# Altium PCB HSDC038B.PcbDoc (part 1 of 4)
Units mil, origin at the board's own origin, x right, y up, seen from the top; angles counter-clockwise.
Board outline 3620 x 4060 mil, 6 copper layers (Top Layer, Signal Layer 1, Signal Layer 2, Signal Layer 3, Signal Layer 4, Bottom Layer), stack 60.4 mil thick; 349 components, 209 nets, 1023 pads, 960 vias.
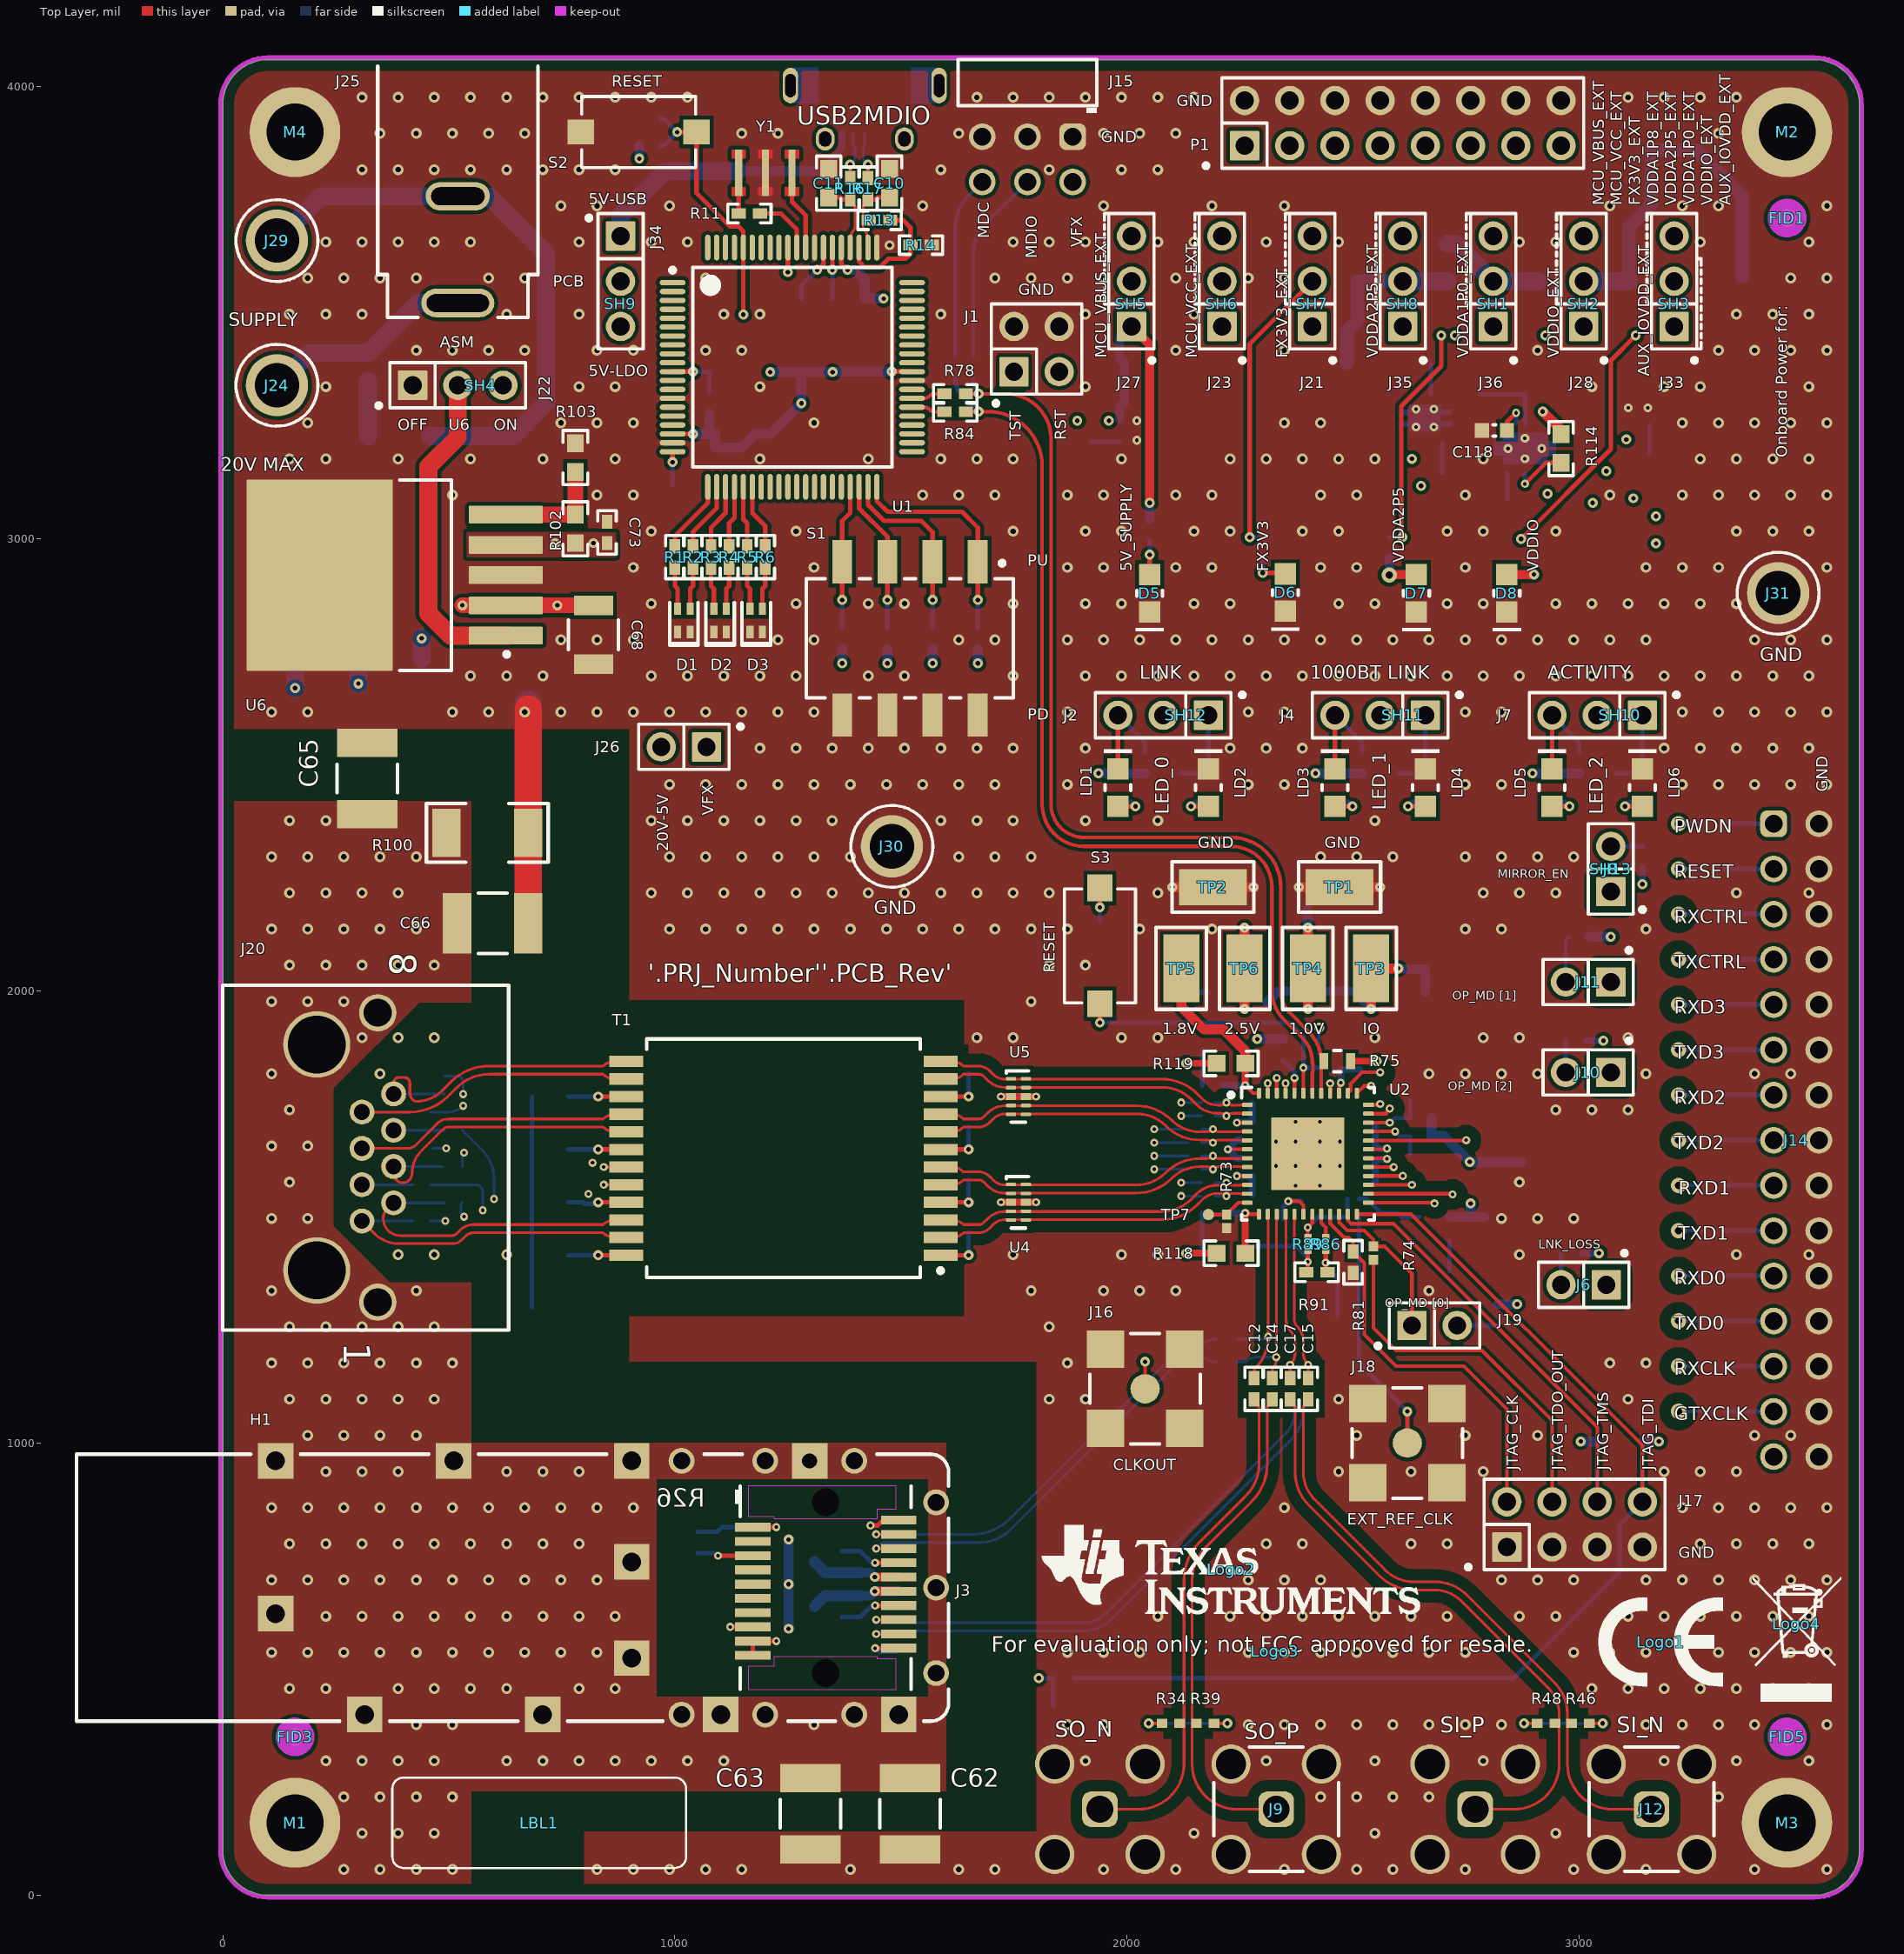
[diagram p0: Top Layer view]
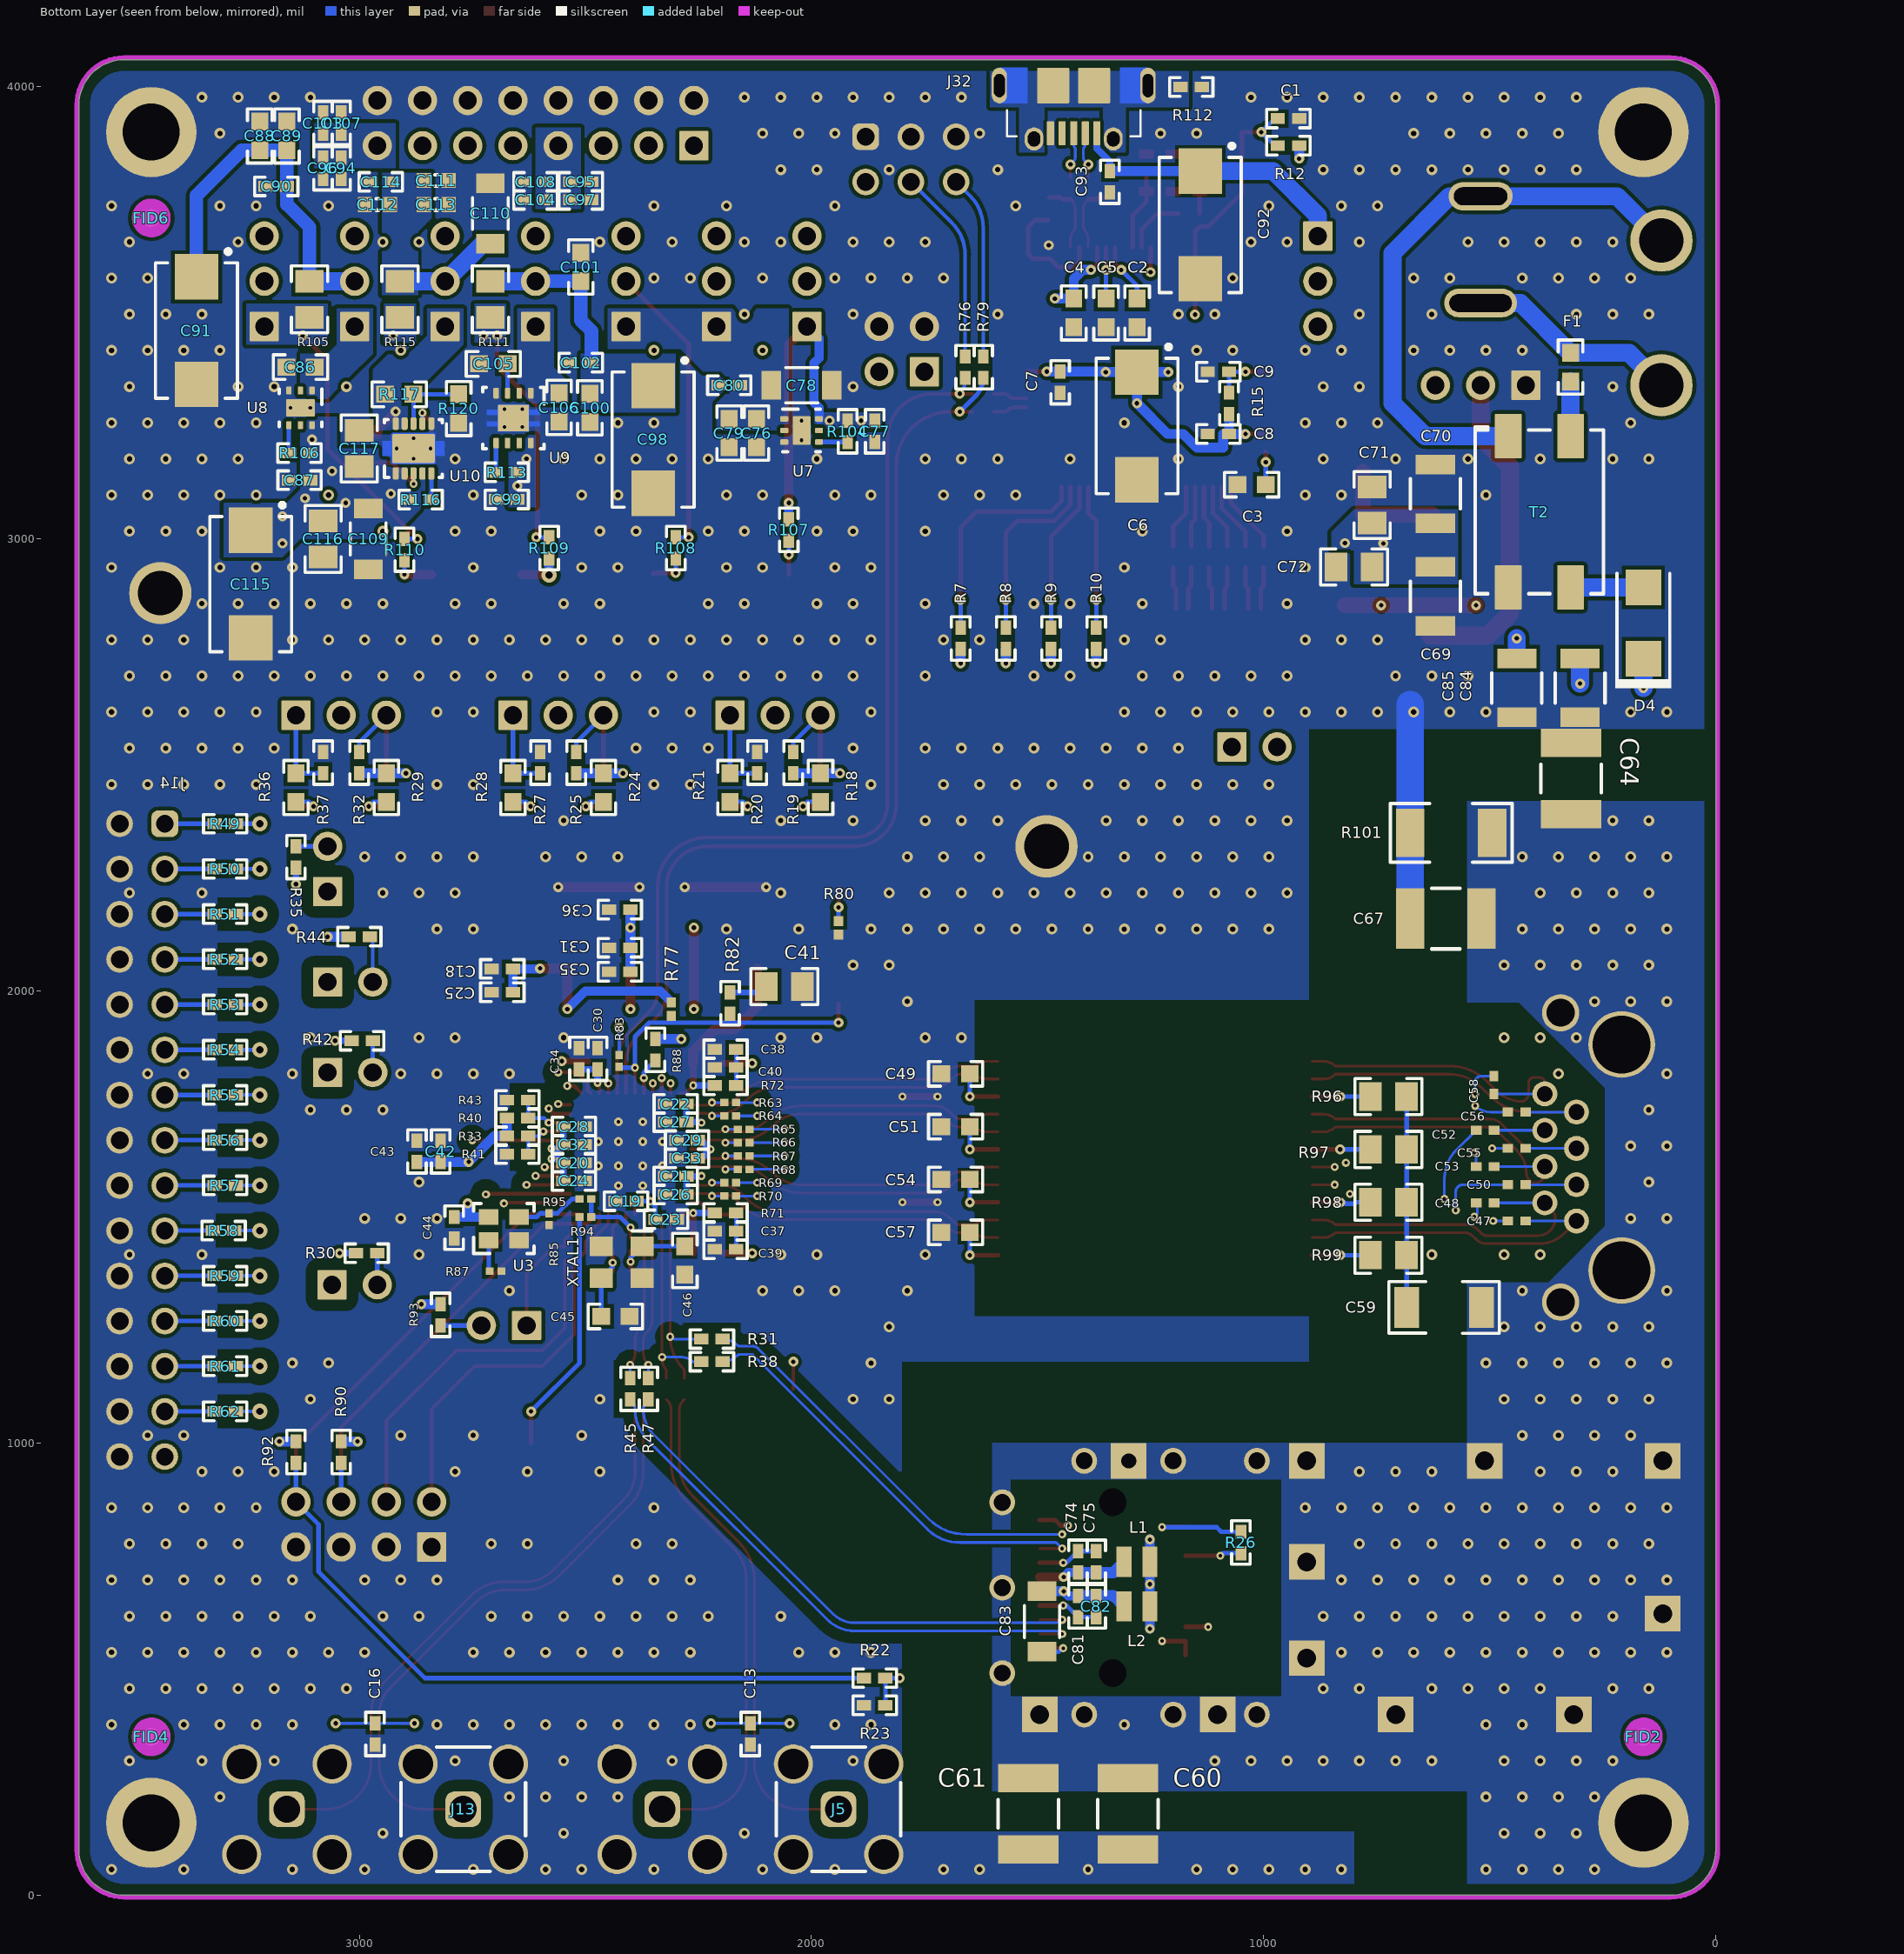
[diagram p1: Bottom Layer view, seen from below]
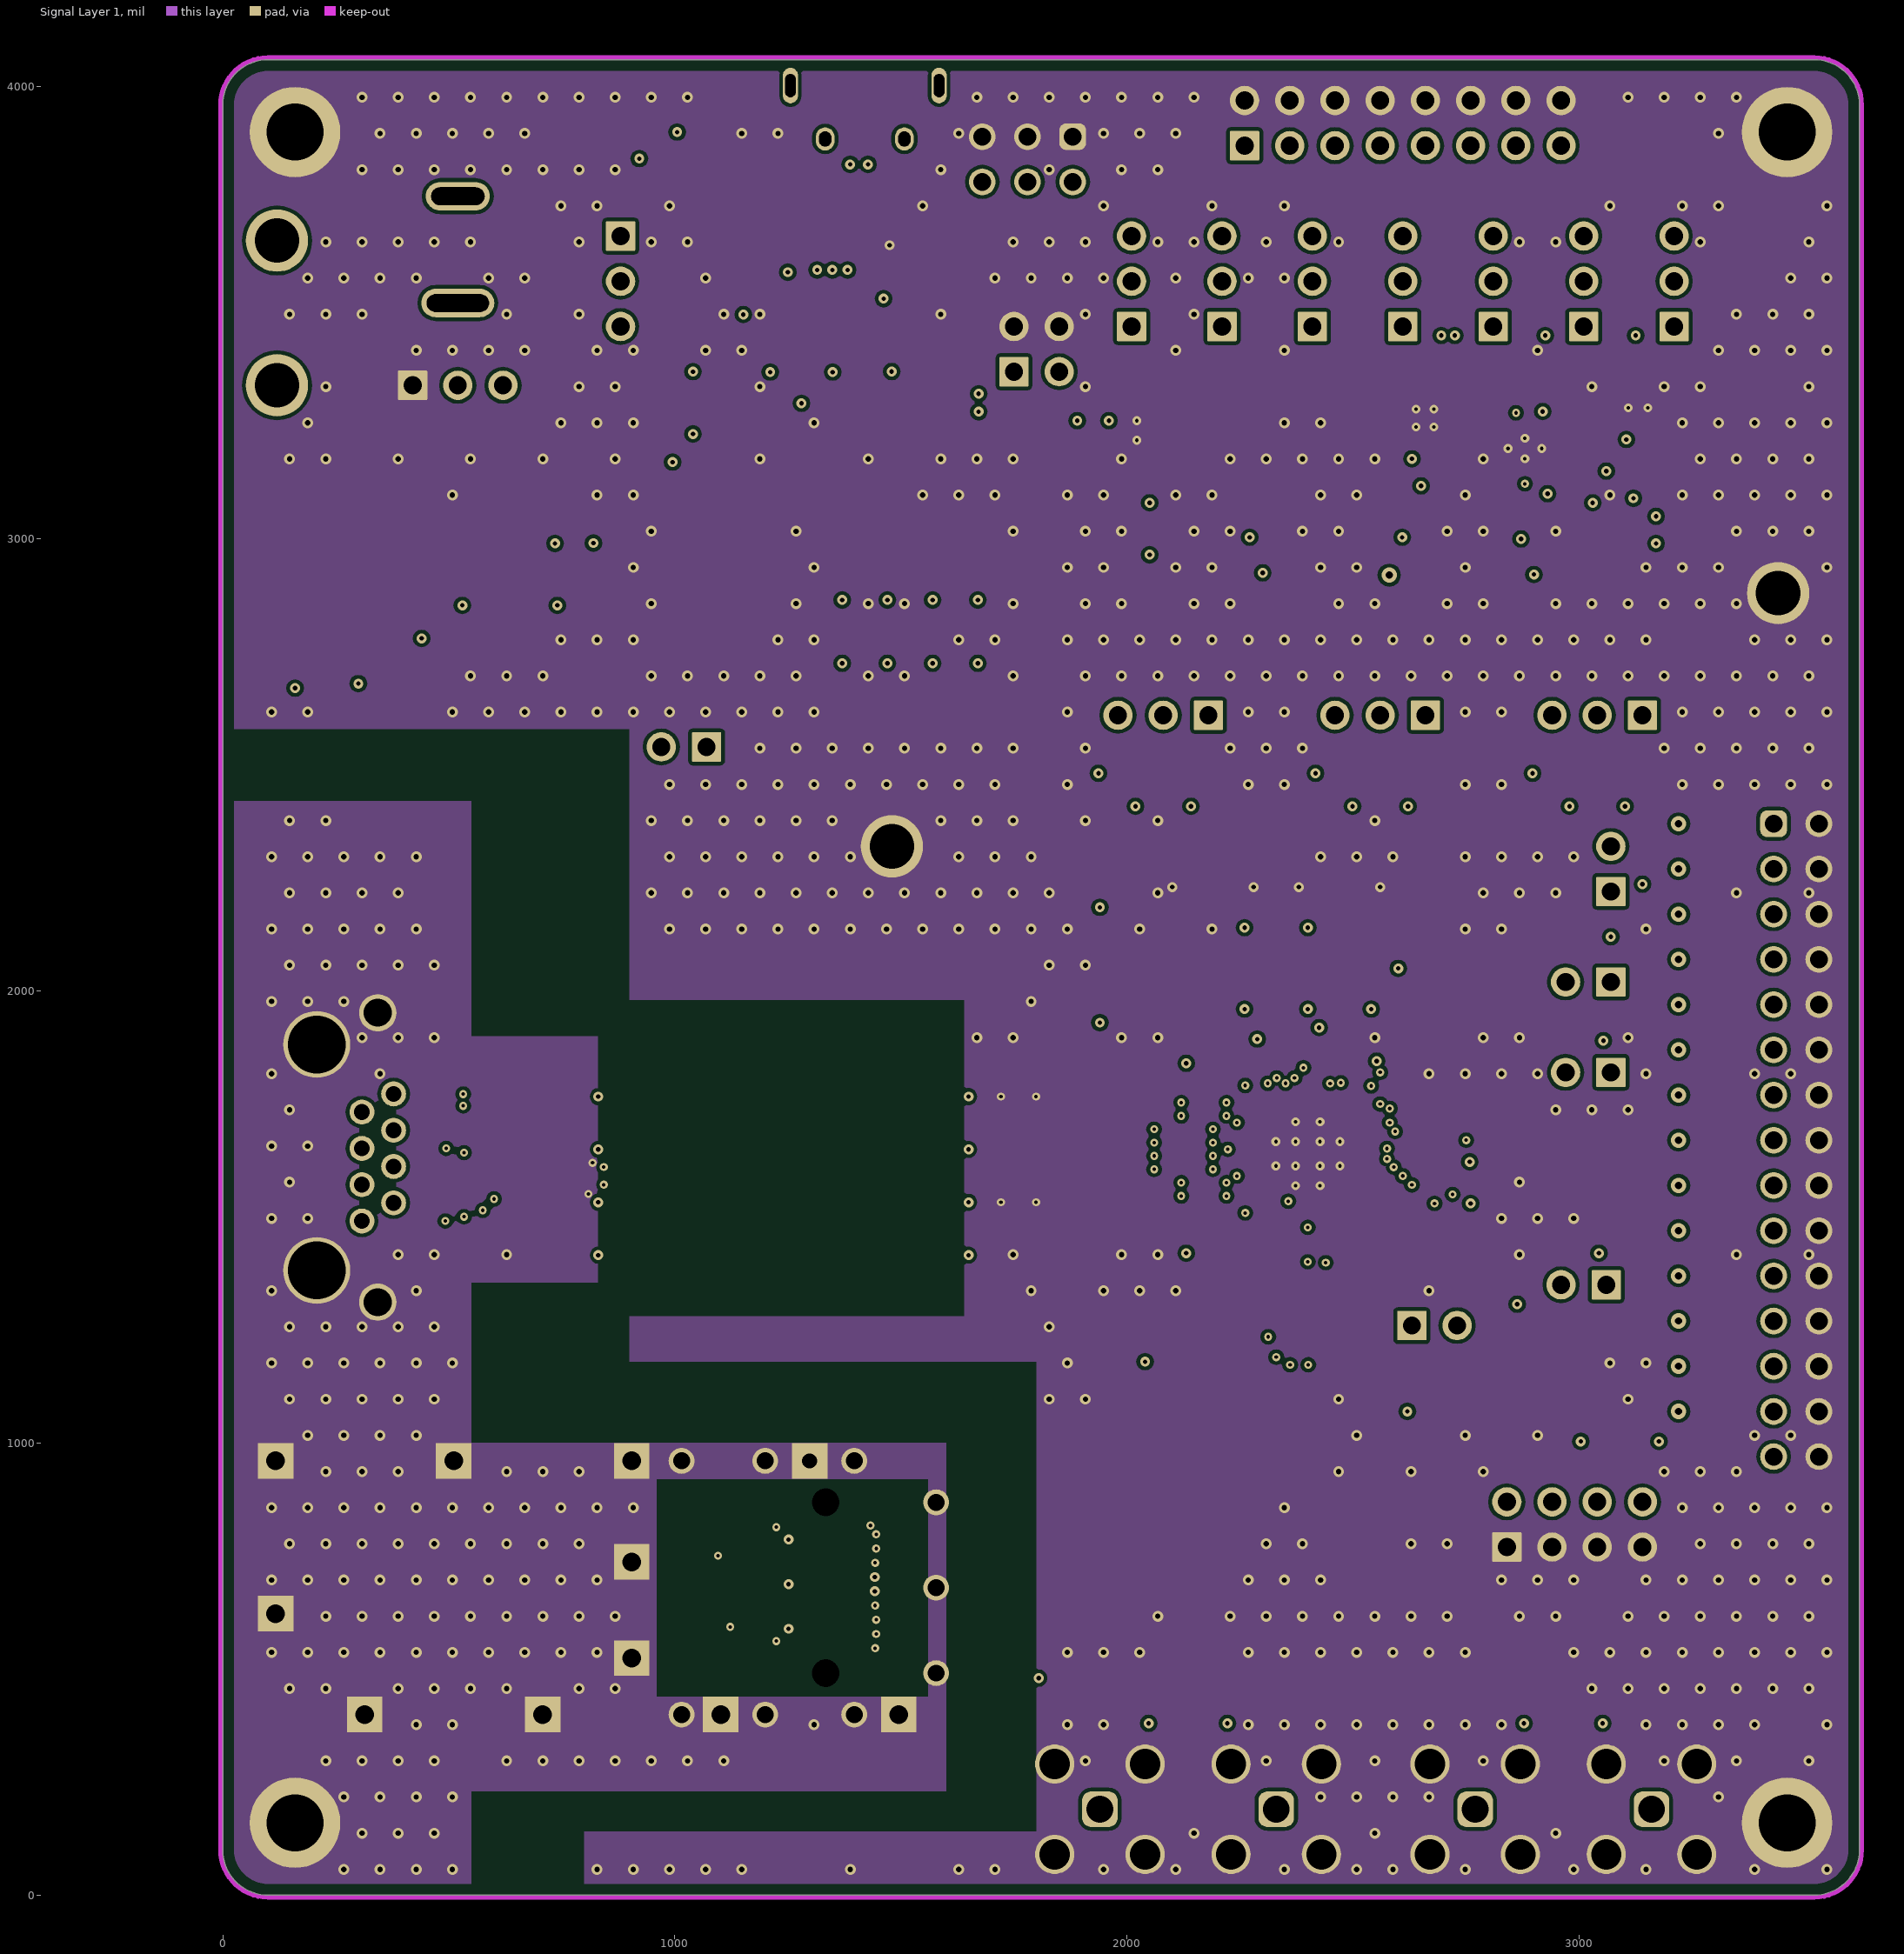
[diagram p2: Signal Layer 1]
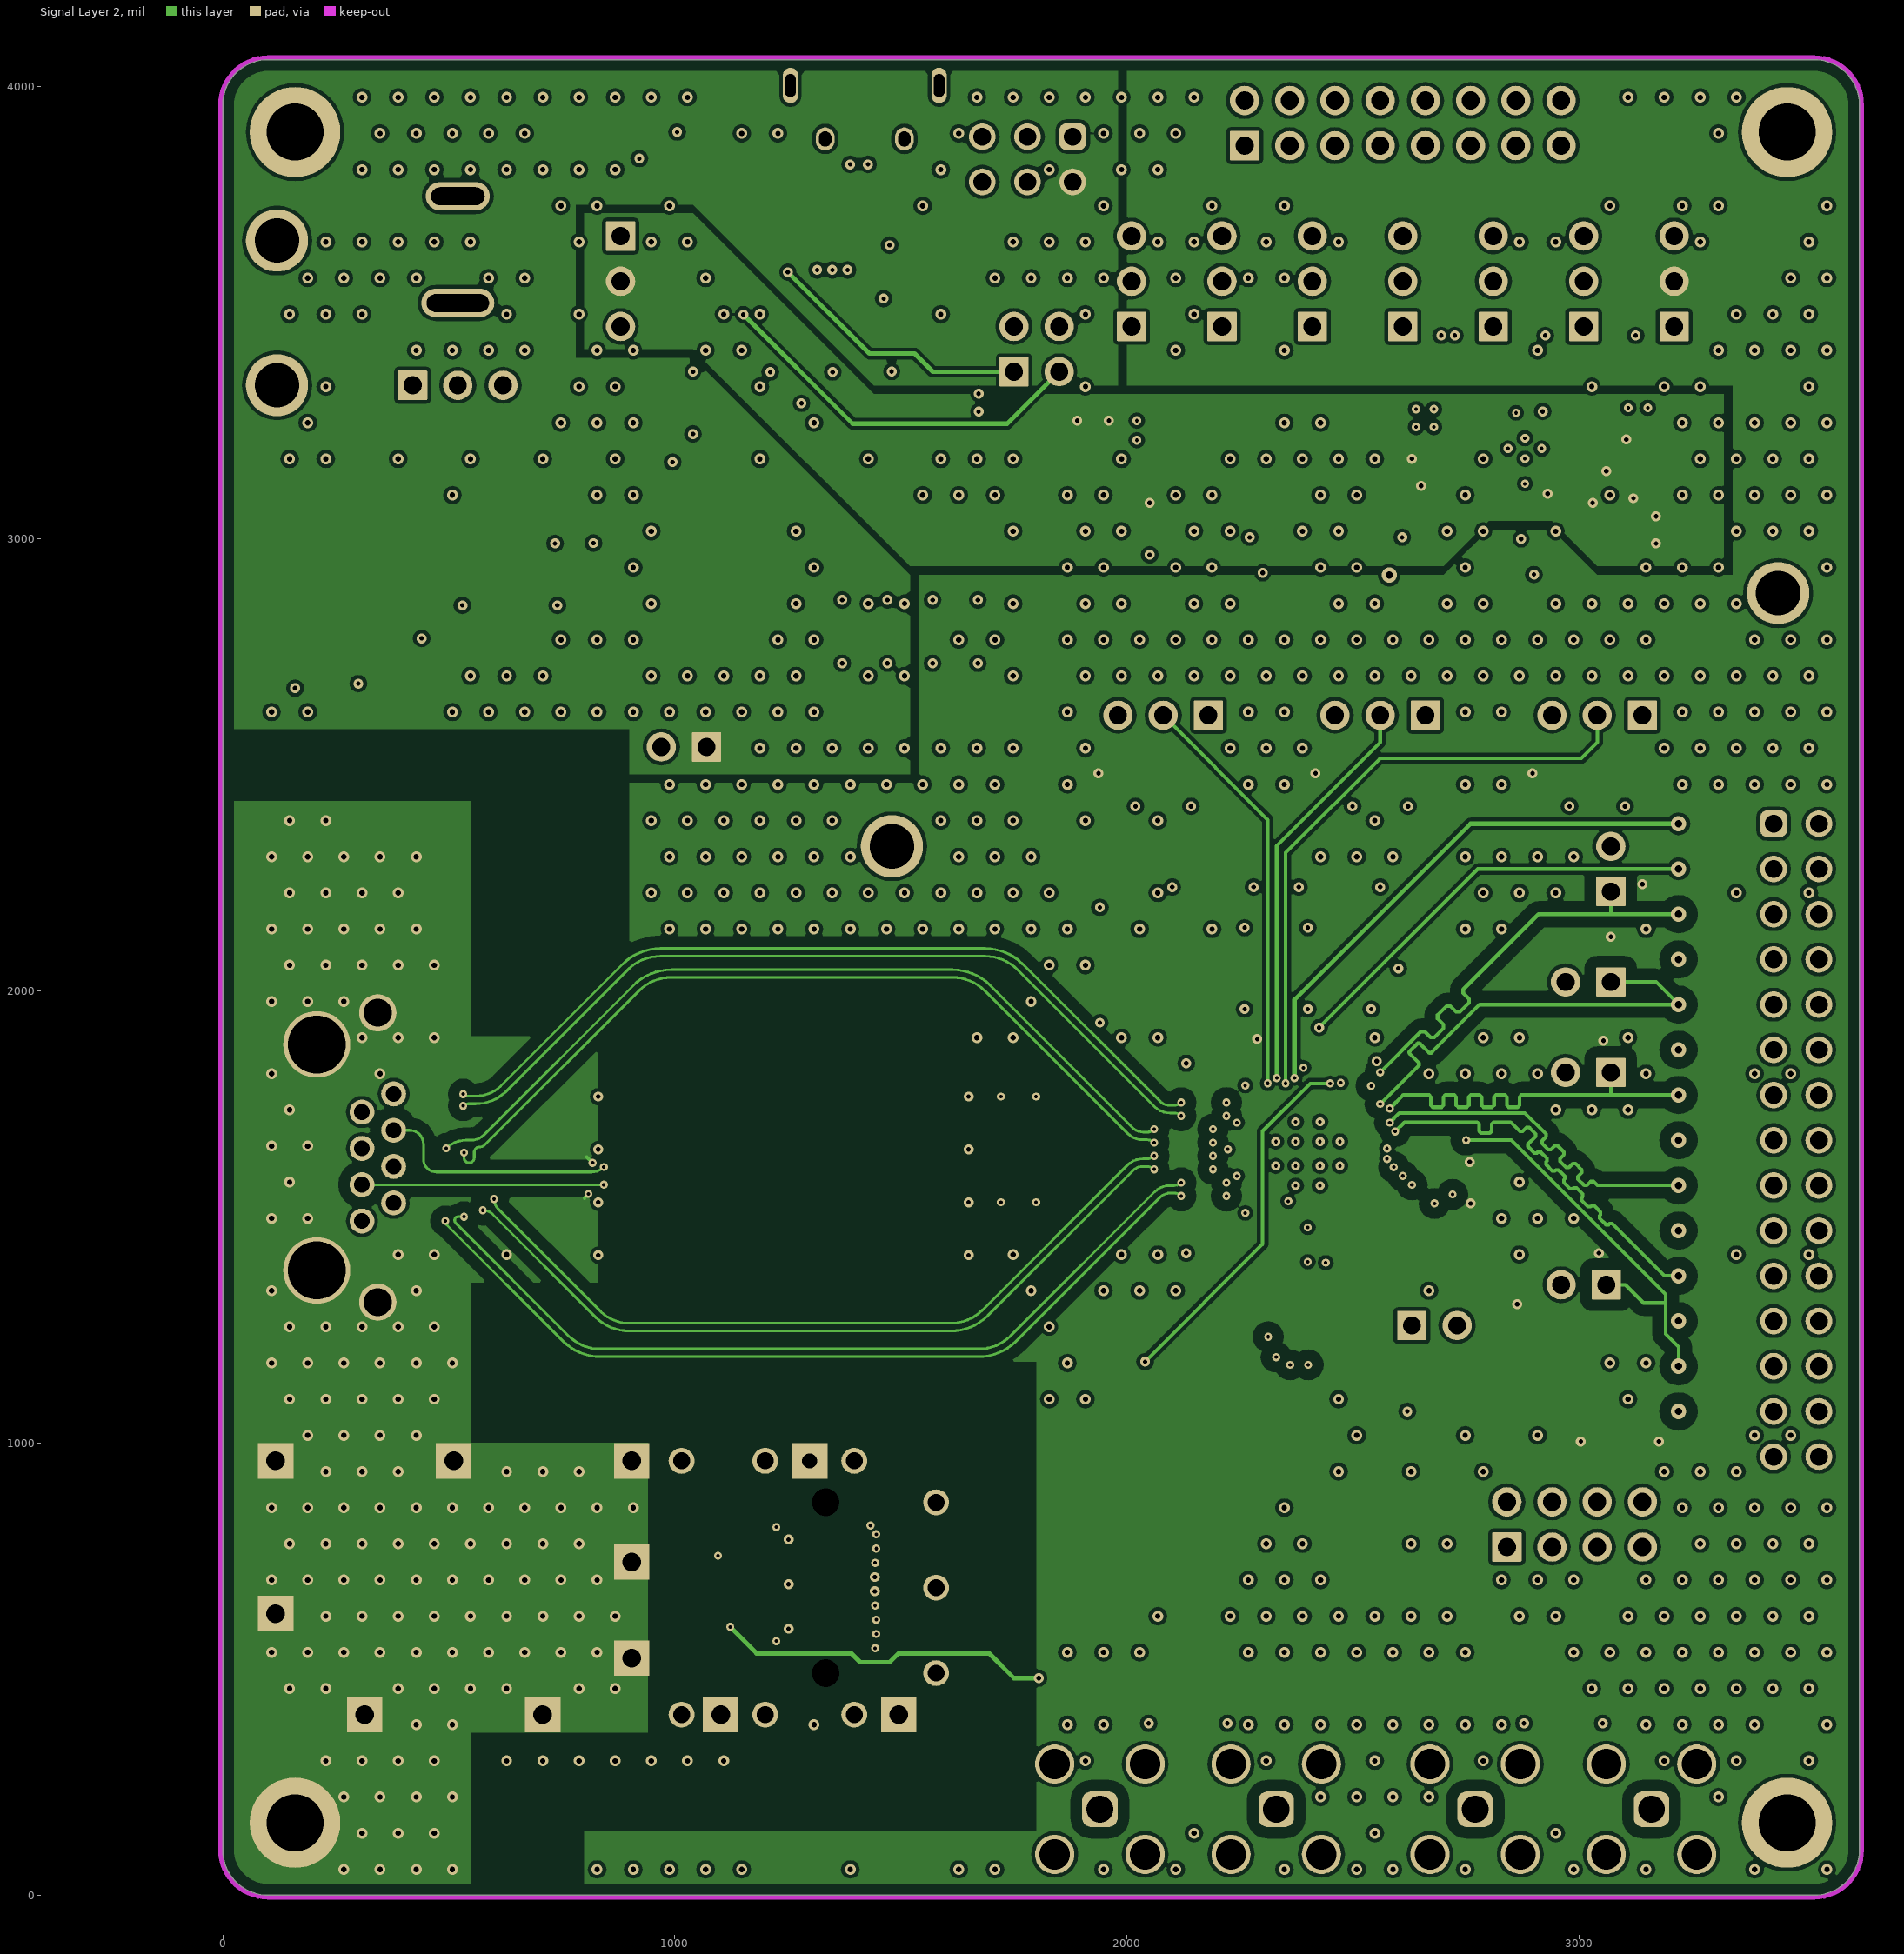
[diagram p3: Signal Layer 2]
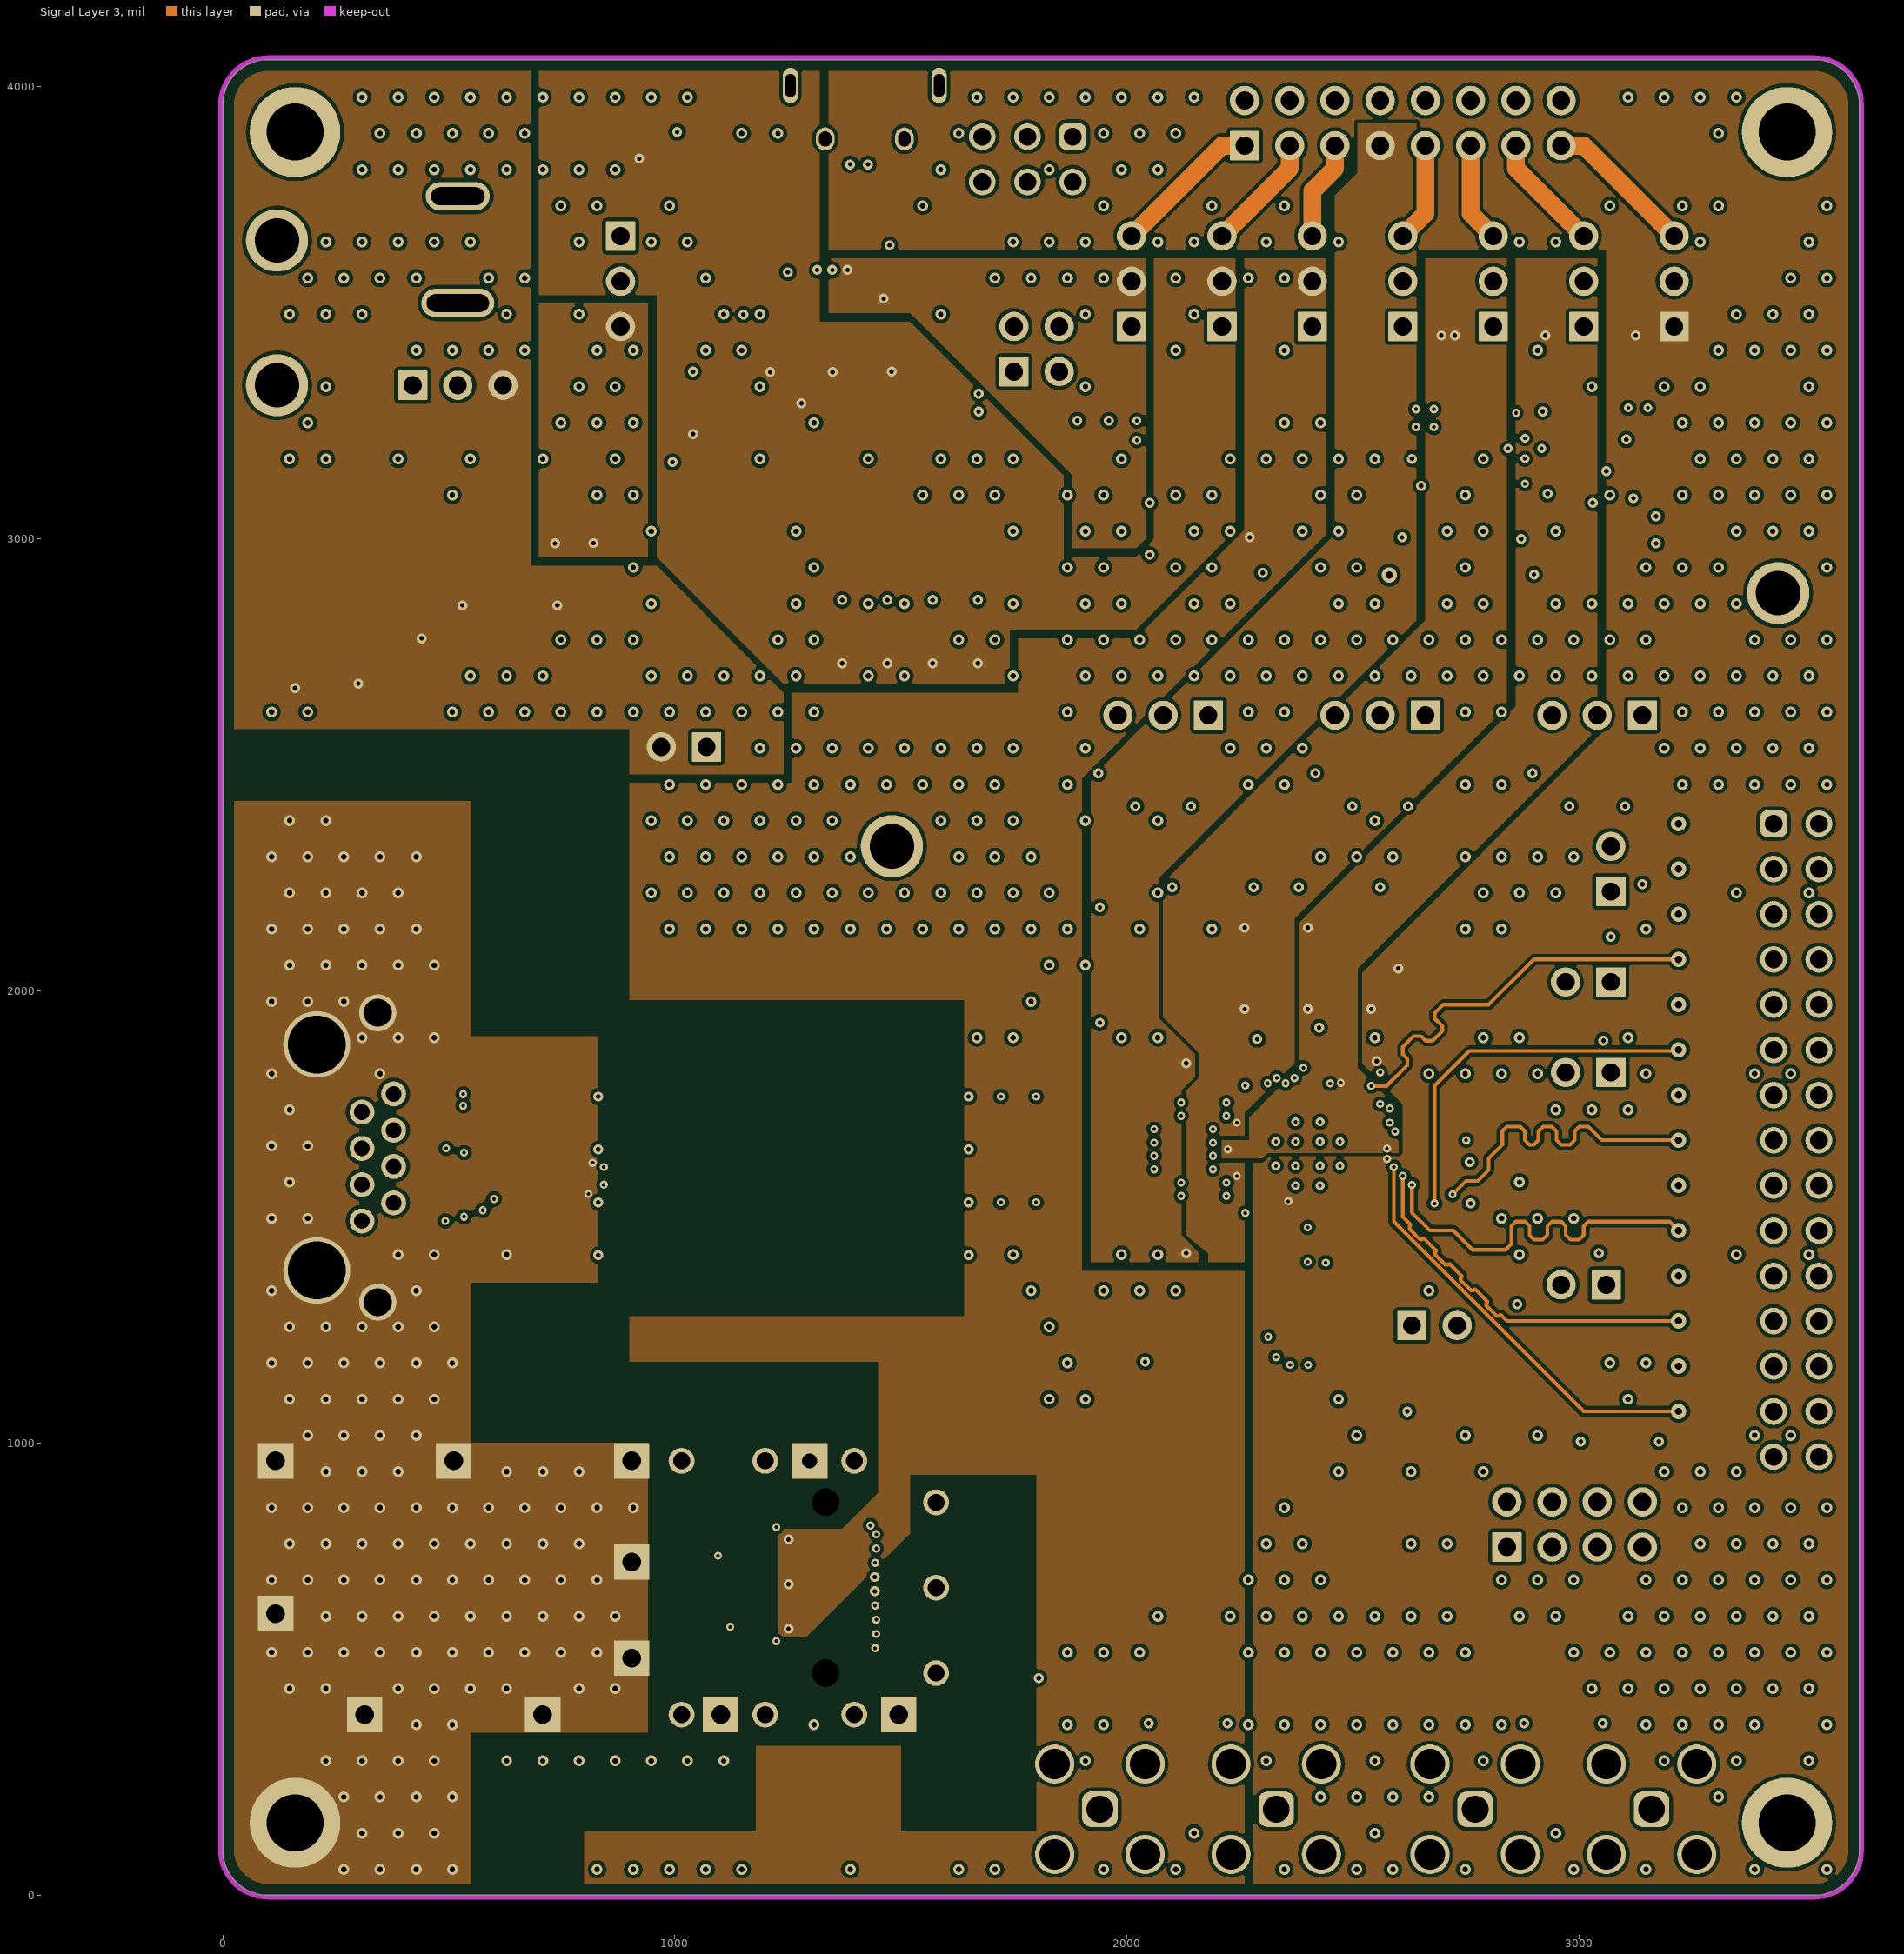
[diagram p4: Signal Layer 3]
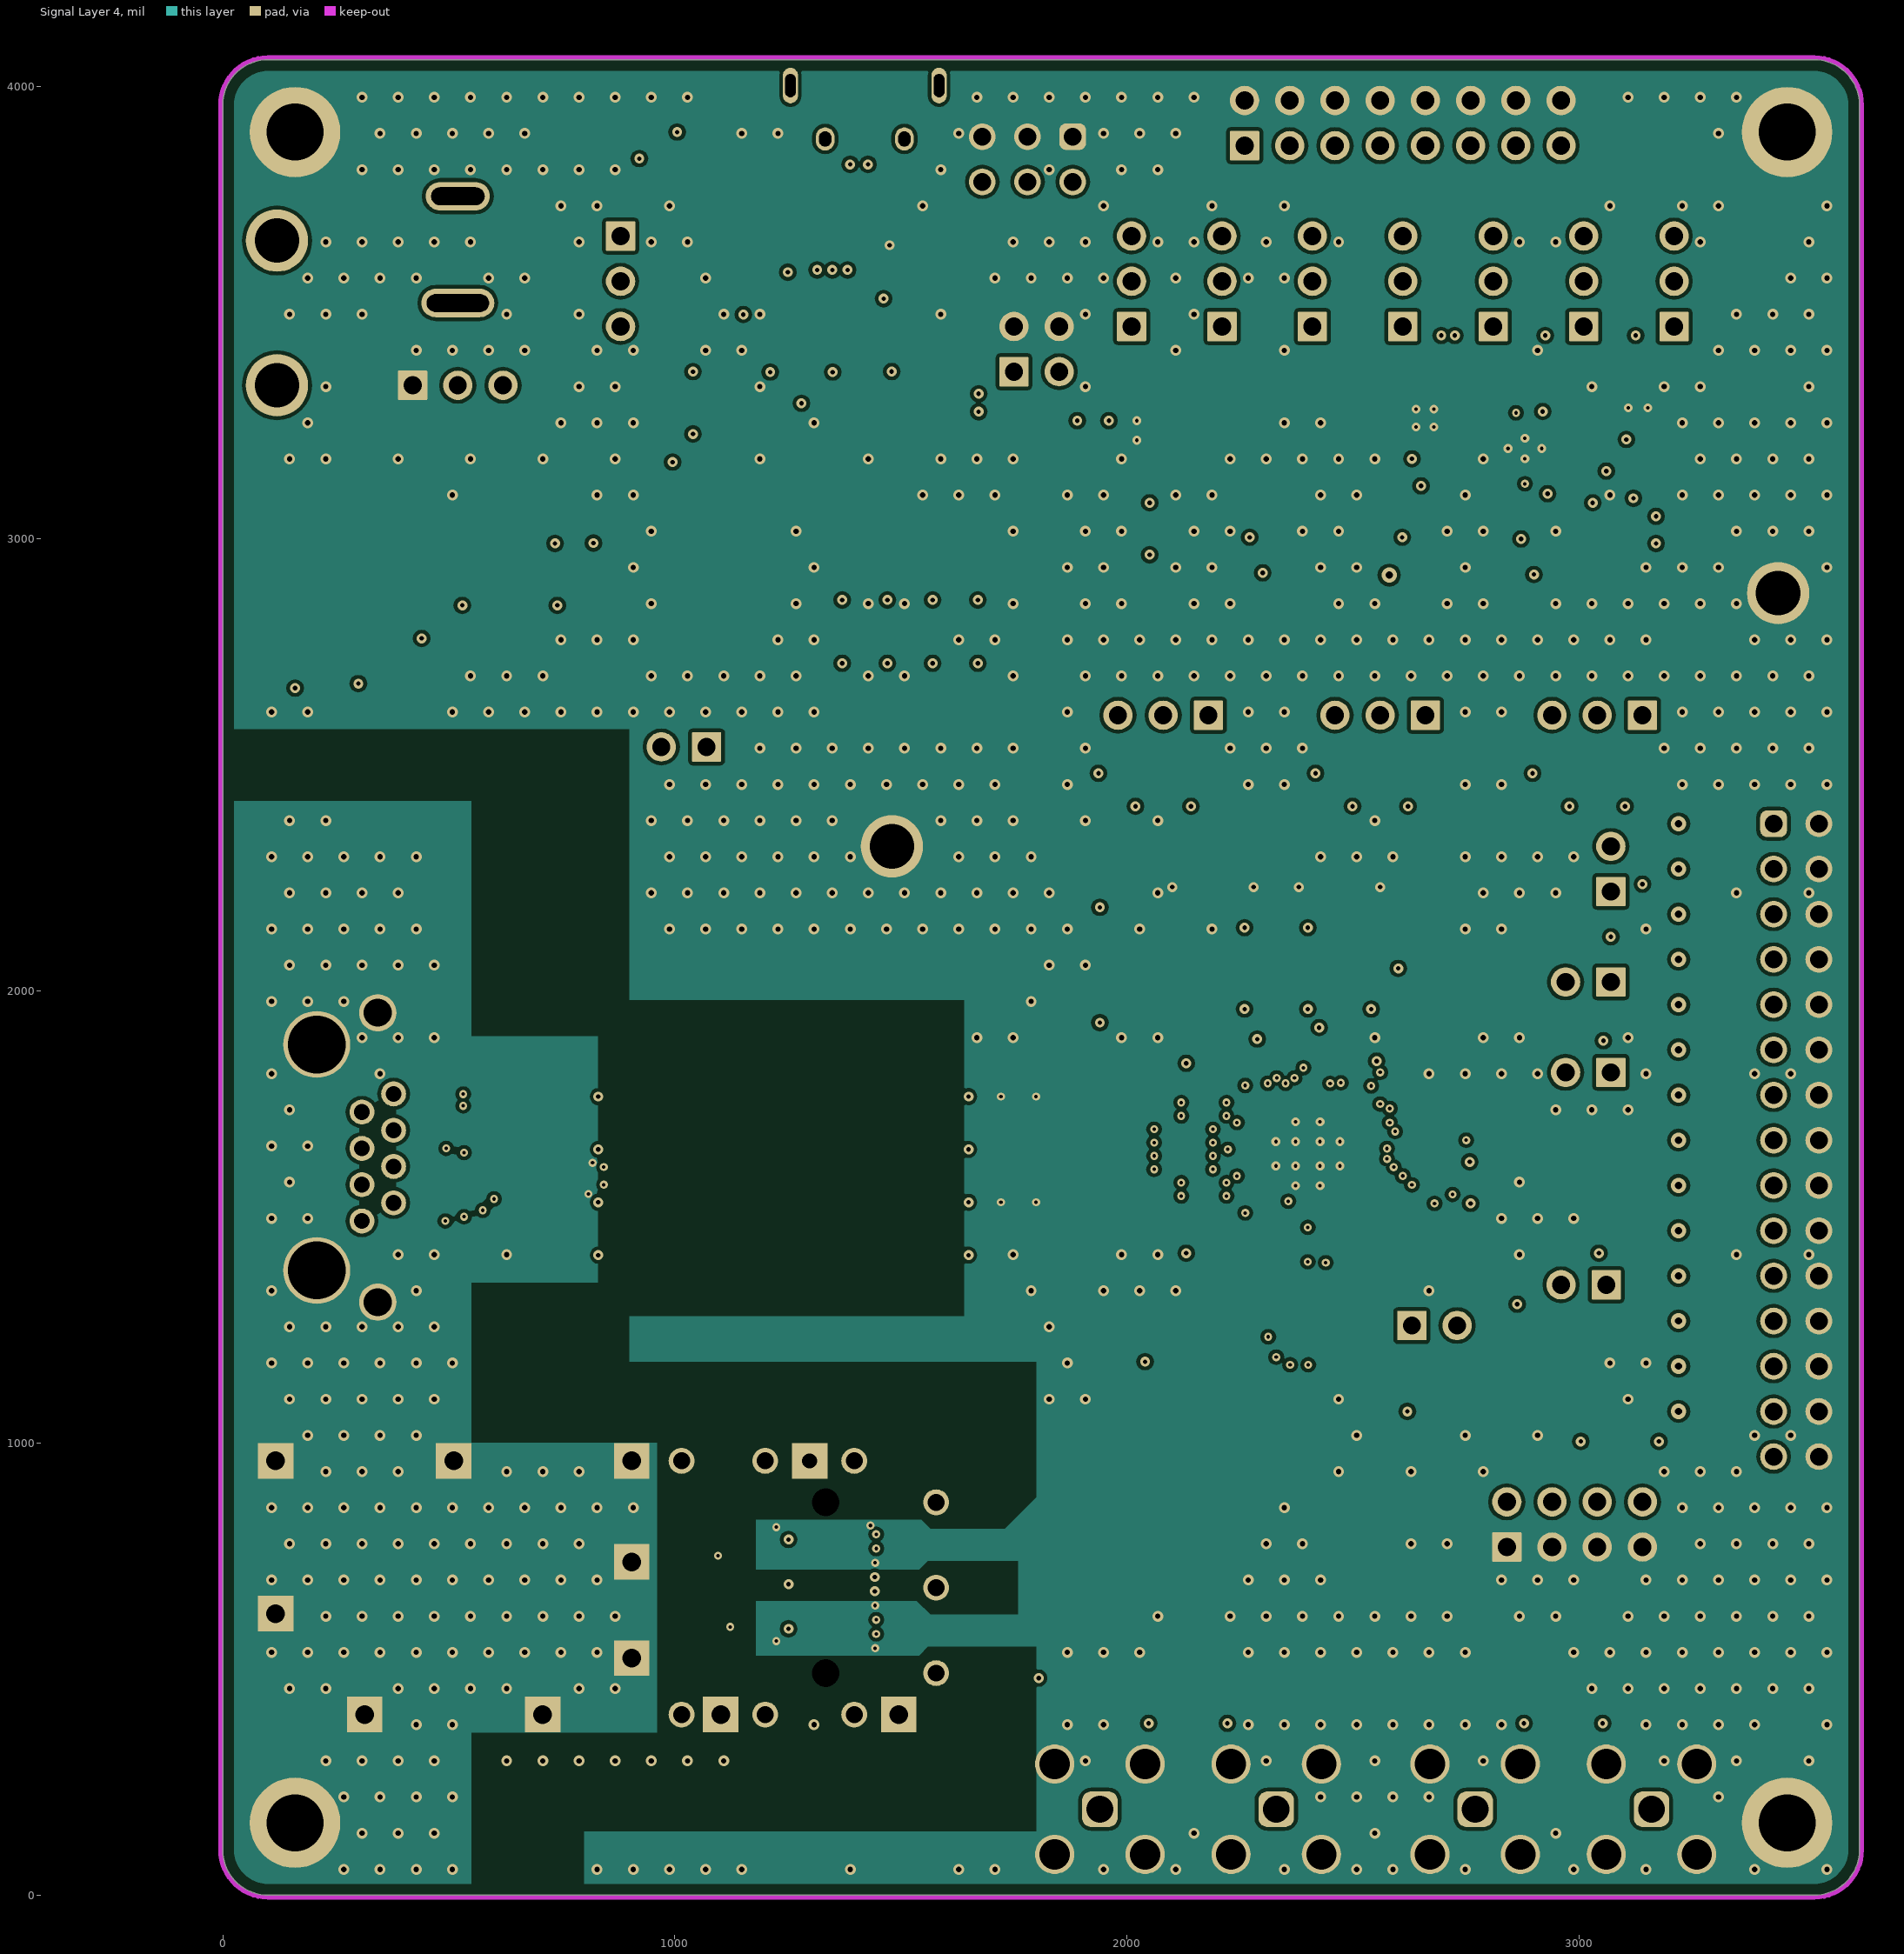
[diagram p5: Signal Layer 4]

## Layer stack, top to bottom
Top Solder: solder mask 0.7, Solder Resist, Dk 3.5
Top Layer: signal copper 1.4
Dielectric 1: prepreg 5, FR-4, Dk 4.6
Signal Layer 1: signal copper 1.4
Dielectric  2: core 5, FR-4, Dk 4.6
Signal Layer 2: signal copper 1.4
Dielectric 3: prepreg 32, FR-4, Dk 4.6
Signal Layer 3: signal copper 1.4
Dielectric 4: core 5, FR-4, Dk 4.6
Signal Layer 4: signal copper 1.4
Dielectric 5: prepreg 5, FR-4, Dk 4.6
Bottom Layer: signal copper 1.4
Bottom Solder: solder mask 0.7, Solder Resist, Dk 3.5

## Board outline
100,0 cw(c100,100) 0,100 0,3960 cw(c100,3960) 100,4060 3520,4060 cw(c3520,3960) 3620,3960 3620,100 cw(c3520,100) 3520,0
cut-out: -692,-1543 -682,-1543 -682,-1533 -692,-1533

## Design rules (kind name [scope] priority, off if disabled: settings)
AcuteAngle [All] p1: minimum=4.50000000000000E+0001 checktracksonly=FALSE
AssemblyTestPointUsage [All] p1: valid=2
BoardOutlineClearance BoardOutlineClearance_MountingHoles [OnCopper and InComponentClass('Mounting Holes')] p1: gap=40 ignorepadtopadclearanceinfootprint=FALSE
BoardOutlineClearance BoardOutlineClearance_Poly [OnCopper and IsPoly] p2: gap=25 ignorepadtopadclearanceinfootprint=FALSE
BoardOutlineClearance [OnCopper and Not InComponentClass('Logo') and not InComponentClass('FiducialMark') and not InRegion(1000,500,4000,800) and not InPoly] p3: gap=75 ignorepadtopadclearanceinfootprint=FALSE
Clearance Clearance_Fiber [InComponent('J3') vs InComponent('J3')] p1: gap=0 ignorepadtopadclearanceinfootprint=TRUE
Clearance Clearance_DiffPair_Polly [InNamedPolygon('Top Layer-GND Net') OR InNamedPolygon('AUX_IOVDD_L03_P081') OR InNamedPolygon('Bottom Layer-GND Net') OR InNamedPolygon('Signal Layer 2-Earth GND') vs InNet('TP_CH3_N') OR InNet('TP_CH3_P') OR InNet('CONN_SO_N') OR InNet('CONN_SO_P') OR InNet('CONN_SI_N') OR InNet('CONN_SI_P') OR InNet('SGMII_SO_N') OR InNet('SGMII_SO_P') OR InNet('SGMII_SI_N') OR InNet('SGMII_SI_P') OR  InNet('FX_SI_N') OR InNet('FX_SI_P') OR InNet('FX_SO_N') OR InNet('FX_SO_P') OR InNet('TD_A_N') OR InNet('TD_A_P') OR InNet('TD_B_N') OR InNet('TD_B_P') OR InNet('TD_C_N') OR InNet('TD_C_P') OR InNet('TD_D_N') OR InNet('TD_D_P') OR InNet('CAP_TD_A_N') OR InNet('CAP_TD_A_P') OR InNet('CAP_TD_B_N') OR InNet('CAP_TD_B_P') OR InNet('CAP_TD_C_N') OR InNet('CAP_TD_C_P') OR InNet('CAP_TD_D_N') OR InNet('CAP_TD_D_P') OR InNet('RX_CTRL') OR InNet('TX_CTRL') OR InNet('RX_D3') OR InNet('RX_D2') OR InNet('RX_D1') OR InNet('RX_D0') OR InNet('RX_CLK') OR InNet('GTX_CLK') OR InNet('TX_D0') OR InNet('TX_D1') OR InNet('TX_D2') OR InNet('TX_D3')] p2: gap=25 ignorepadtopadclearanceinfootprint=FALSE except(0: Arc-Hole Track-Hole SMDPad-Hole THPad-Hole Via-Hole Fill-Hole Poly-Hole Region-Hole Text-Hole)
Clearance Clearance_Keepouts [((IsTrack Or IsArc) And Not InPoly) And IsFree and IsKeepOut vs ((IsTrack Or IsArc) And Not InPoly) And IsFree and IsKeepOut] p3: gap=0 ignorepadtopadclearanceinfootprint=FALSE
Clearance Clearance_Poly [InPolygon] p4: gap=8 ignorepadtopadclearanceinfootprint=FALSE except(0: Arc-Hole Track-Hole SMDPad-Hole THPad-Hole Via-Hole Fill-Hole Poly-Hole Region-Hole Text-Hole)
Clearance Clearance_FiducialMark [IsKeepOut and InComponentClass('FiducialMark') vs IsPad and InComponentClass('FiducialMark')] p5: gap=0 ignorepadtopadclearanceinfootprint=FALSE
Clearance Clearance_TightSpace [All vs TouchesRoom('TightSpace1') OR TouchesRoom('HSDC038B_Power_Supply') OR TouchesRoom('HSDC038B_Hardware')  OR TouchesRoom('HSDC038A_Magnetics')] p6: gap=5 ignorepadtopadclearanceinfootprint=TRUE except(0: Arc-Hole Track-Hole SMDPad-Hole THPad-Hole Via-Hole Fill-Hole Poly-Hole Region-Hole Text-Hole)
Clearance [All] p7: gap=7.87 ignorepadtopadclearanceinfootprint=TRUE except(0: Arc-Hole Track-Hole SMDPad-Hole THPad-Hole Via-Hole Fill-Hole Poly-Hole Region-Hole Text-Hole)
ComponentClearance ComponentClearance_Shunt [InComponentClass('Header') OR InComponent('J30') vs InComponentClass('Shunt')] p1: gap=0 collisioncheckmode=3 verticalgap=0 showdistances=FALSE
ComponentClearance ComponentClearance_Fiducial [InComponent('H1') vs InComponentClass('FiducialMark')] p2: gap=0 collisioncheckmode=3 verticalgap=0 showdistances=FALSE
ComponentClearance ComponentClearance_Fiber [InComponent('J3') vs InComponent('H1')] p3: gap=0 collisioncheckmode=3 verticalgap=0 showdistances=FALSE
ComponentClearance ComponentClearance_MountingHoles_FiducialMarks [InComponentClass('Mounting Holes') vs InComponentClass('FiducialMark')] p4: gap=50 collisioncheckmode=3 verticalgap=10 showdistances=FALSE
ComponentClearance ComponentClearance_Logo [InComponentClass('Logo')] p5: gap=50 collisioncheckmode=3 verticalgap=10 showdistances=FALSE
ComponentClearance ComponentClearance_ScrewToNut [(HasFootprint('NY PMS 440 0025 PH')) vs (HasFootprint('Keystone_1902C'))] p6: gap=5 collisioncheckmode=3 verticalgap=10 showdistances=FALSE
ComponentClearance ComponentClearance_MountingHoles [InComponentClass('Mounting Holes')] p7: gap=250 collisioncheckmode=3 verticalgap=100000 showdistances=FALSE
ComponentClearance ComponentClearance_SmallPassives [HasFootprint('0201*') or HasFootprint('0402*') or HasFootprint('0508') or HasFootprint('0603*') or HasFootprint('0612') or HasFootprint('0805*') or HasFootprint('0815*') or HasFootprint('0830*') or HasFootprint('1206*') or HasFootprint('1210*') or HasFootprint('1808*') or HasFootprint('1812*') or HasFootprint('1825*') or HasFootprint('2010*') or HasFootprint('2220*') or HasFootprint('2225*') or HasFootprint('2512*') or HasFootprint('2728*') or HasFootprint('3518*') vs HasFootprint('0201*') or HasFootprint('0402*') or HasFootprint('0508') or HasFootprint('0603*') or HasFootprint('0612') or HasFootprint('0805*') or HasFootprint('0815*') or HasFootprint('0830*') or HasFootprint('1206*') or HasFootprint('1210*') or HasFootprint('1808*') or HasFootprint('1812*') or HasFootprint('1825*') or HasFootprint('2010*') or HasFootprint('2220*') or HasFootprint('2225*') or HasFootprint('2512*') or HasFootprint('2728*') or HasFootprint('3518*')] p8: gap=10 collisioncheckmode=3 verticalgap=10 showdistances=FALSE
ComponentClearance ComponentClearance_THtoSMT [IsThruComponent vs IsSMTComponent] p9: gap=30 collisioncheckmode=3 verticalgap=30 showdistances=FALSE
ComponentClearance ComponentClearance_THtoTH [IsThruComponent vs IsThruComponent] p10: gap=40 collisioncheckmode=3 verticalgap=30 showdistances=FALSE
ComponentClearance [All] p11: gap=20 collisioncheckmode=3 verticalgap=10 showdistances=FALSE
DiffPairsRouting [All] p1: maxlimit=100 minlimit=11 mostfreqgap=12 toplayer_mingap=12 toplayer_minwidth=6 toplayer_maxwidth=10 toplayer_prefwidth=6 midlayer1_mingap=14 midlayer1_prefgap=14 midlayer1_minwidth=4 midlayer1_maxwidth=10 midlayer1_prefwidth=4.5 midlayer2_prefgap=11 midlayer2_minwidth=6 midlayer2_maxwidth=10 midlayer2_prefwidth=6 midlayer3_minwidth=6 midlayer3_maxwidth=10 midlayer3_prefwidth=6 midlayer6_mingap=14 midlayer6_prefgap=14 midlayer6_minwidth=4 midlayer6_maxwidth=10 midlayer6_prefwidth=4.5 bottomlayer_mingap=12 bottomlayer_minwidth=6 bottomlayer_maxwidth=10 bottomlayer_prefwidth=6 maxuncoupledlength=1000
FabricationTestPointUsage TestPointUsage [All] p1: valid=2 allowmultiple=FALSE
FabricationTestpoint Testpoint [All] p1: side=3 testpointundercomponent=TRUE minsize=40 maxsize=100 preferedsize=60 minholesize=0 maxholesize=40 preferedholesize=32 testpointgrid=1 allowsidetop=TRUE allowsidebottom=TRUE usegrid=TRUE gridtolerance=0.01
FanoutControl Fanout_LCC [IsLCC] p1: bgadir=Out bgaviamode=Centered fanoutstyle=Auto fanoutdirection=Alternating viagrid=1 // Fanout_LCC (Default Rule)
FanoutControl Fanout_BGA [IsBGA] p2: bgadir=Out bgaviamode=Centered fanoutstyle=Auto fanoutdirection=Alternating viagrid=1 // Fanout_BGA (Default Rule)
FanoutControl Fanout_Default [All] p4: bgadir=Out bgaviamode=Centered fanoutstyle=Auto fanoutdirection=Alternating viagrid=1 // Fanout_Default (Default Rule)
FanoutControl Fanout_Small [(CompPinCount < 5)] p5: bgadir=Out bgaviamode=Centered fanoutstyle=Auto fanoutdirection=OutThenIn viagrid=1 // Fanout_Small (Default Rule)
HoleSize [All] p1: absolutevalues=TRUE maxlimit=251 minlimit=7.87 maxpercent=80.000 minpercent=20.000
MatchedLengths MatchedLengths_RGMIITX [InNetClass('RGMII_TX')] p1: tolerance=150 checknetsindiffpair=FALSE checkdiffpairvsdiffpair=TRUE checkxsignals=TRUE checkothers=TRUE
MatchedLengths MatchedLengths_RGMIIRX [InNetClass('RGMII_RX')] p2: tolerance=200 checknetsindiffpair=FALSE checkdiffpairvsdiffpair=TRUE checkxsignals=TRUE checkothers=TRUE
MinimumAnnularRing MinimumAnnularRing_ThermalPadVias [IsVia and InAnyComponent] p1: minimumring=5
MinimumAnnularRing [All] p2: minimumring=5
MinimumSolderMaskSliver MinimumSolderMaskSliver_Logo [InComponentClass('Logo') vs InComponentClass('Logo')] p1: minsoldermaskwidth=0.7
MinimumSolderMaskSliver [All] p2: minsoldermaskwidth=3.94
PlaneConnect [All] p1: planeconnectstyle=Relief reliefexpansion=10 reliefentries=4 reliefconductorwidth=10 reliefairgap=10
PolygonConnect [All] p1: connectstyle=Direct reliefconductorwidth=10 reliefentries=4 polygonreliefangle="90 Angle" airgapwidth=10
RoomDefinition HSDC038A_Magnetics [InComponentClass('HSDC038A_Magnetics')] p1 off: confinementstyle=ConfineOut formatcopy=TRUE lockcomponents=FALSE outline 1400,860 1480,860 1480,520 1400,520
RoomDefinition HSDC038B_Hardware [InComponentClass('HSDC038B_Hardware')] p2 off: confinementstyle=ConfineIn formatcopy=TRUE lockcomponents=FALSE outline 2300,1860 2620,1860 2620,1360 2300,1360
RoomDefinition TightSpace1 [InComponentClass('Components Class 1')] p3 off: confinementstyle=ConfineIn formatcopy=TRUE lockcomponents=FALSE outline 2800,3280 2960,3280 2960,3120 2800,3120
RoutingVias ThermalPadVias [IsVia and InAnyComponent] p1: holewidth=7.87 width=19.68 viastyle="Through Hole" minholewidth=7.87 minwidth=17.87 maxholewidth=12.99 maxwidth=23.62
RoutingVias [All] p2: holewidth=16 width=34 viastyle="Through Hole" minholewidth=7.87 minwidth=17.87 maxholewidth=40 maxwidth=65
SilkToSilkClearance SilkToSilkClearance_Pb-FreeLogo [(HasFootprint('Pb-Free_Overlay_Medium') OR HasFootprint('Pb-Free_Overlay_Small')) vs (HasFootprint('Pb-Free_Overlay_Medium') OR HasFootprint('Pb-Free_Overlay_Small'))] p1: silktosilkclearance=0
SilkToSilkClearance [All] p2: silktosilkclearance=3
SilkToSolderMaskClearance SilkToComponentPadClearance [(IsPad or IsFill or IsRegion) and InAnycomponent] p1: minsilkscreentomaskgap=3 clearancetoexposedcopper=TRUE
SilkToSolderMaskClearance "Silk to Solder Mask Opening" [All] p2: minsilkscreentomaskgap=3 clearancetoexposedcopper=FALSE
SolderMaskExpansion [All] p1: expansion=1.97
Width [All] p1: maxlimit=100 minlimit=6 preferedwidth=10 checkconnectedcopper=TRUE
16 further rules are at their usual default settings.

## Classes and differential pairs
net class RGMII_RX: RX_CLK RX_CTRL RX_D0 RX_D1 RX_D2 RX_D3
net class RGMII_TX: GTX_CLK TX_CTRL TX_D0 TX_D1 TX_D2 TX_D3
component class Shunt: SH1 SH2 SH3 SH4 SH5 SH6 SH7 SH8 SH9 SH10 SH11 SH12 SH13
component class HSDC038B_COMS: C1 C2 C3 C4 C5 C6 C7 C8 C9 C10 C11 D1 D2 D3 J1 R1 R2 R3 R4 R5 R6 R7 R8 R9 R10 R11 R12 R13 R14 R15 R16 R17 S1 S2 U1 Y1
component class HSDC038B_Hardware: FID1 FID2 FID3 FID4 FID5 FID6 LBL1 Logo1 Logo2 Logo3 Logo4 M1 M2 M3 M4 SH1 SH2 SH3 SH4 SH5 SH6 SH7 SH8 SH9 SH10 SH11 SH12 SH13 ZZ1 ZZ2 ZZ3 ZZ4
component class HSDC038B_Power_Supply: 1 C68 C69 C70 C71 C72 C73 C74 C75 C76 C77 C78 C79 C80 C81 C82 C83 C84 C85 C86 C87 C88 C89 C90 C91 C92 C93 C94 C95 C96 C97 C98 C99 C100 C101 C102 C103 C104 C105 C106 C107 C108 C109 C110 C111 C112 C113 C114 C115 C116 C117 C118 D4 D5 D6 D7 D8 F1 J21 J22 J23 J24 J25 J26 J27 J28 J29 J30 J31 J32 J33 J34 J35 J36 J37 J38 J39 L1 L2 LD10 P1 Q2 Q3 R102 R103 R104 R105 R106 R107 R108 R109 R110 R111 R112 R113 R114 R115 R116 R117 R118 R119 R120 T2 Text U6 U7 U8 U9 U10 ZZ8
component class HSDC038B_DP83869: C18 C19 C20 C21 C22 C23 C24 C25 C26 C27 C28 C29 C30 C31 C32 C33 C34 C35 C36 C37 C38 C39 C40 C41 C42 C43 C44 C45 C46 J14 J15 J16 J17 J18 J19 R49 R50 R51 R52 R53 R54 R55 R56 R57 R58 R59 R60 R61 R62 R63 R64 R65 R66 R67 R68 R69 R70 R71 R72 R73 R74 R75 R76 R77 R78 R79 R80 R81 R82 R83 R84 R85 R86 R87 R88 R89 R90 R91 R92 R93 R94 R95 S3 TP1 TP2 TP3 TP4 TP5 TP6 TP7 U2 U3 XTAL1
component class HSDC038B_Configuration_Pins: C12 C13 C14 C15 C16 C17 H1 J2 J3 J4 J5 J6 J7 J8 J9 J10 J11 J12 J13 LD1 LD2 LD3 LD4 LD5 LD6 R18 R19 R20 R21 R22 R23 R24 R25 R26 R27 R28 R29 R30 R31 R32 R33 R34 R35 R36 R37 R38 R39 R40 R41 R42 R43 R44 R45 R46 R47 R48 SH-J1
component class Header: J1 J2 J4 J6 J7 J8 J10 J11 J14 J15 J17 J19 J21 J22 J23 J26 J27 J28 J33 J34 J35 J36 P1
component class Logo: Logo2
component class HSDC038B_Magnetics: C47 C48 C49 C50 C51 C52 C53 C54 C55 C56 C57 C58 C59 C60 C61 C62 C63 C64 C65 C66 C67 J20 R96 R97 R98 R99 R100 R101 T1 U4 U5
component class FiducialMark: FID1 FID2 FID3 FID4 FID5 FID6
component class Label: LBL1
component class AssemblyNote: ZZ1 ZZ2 ZZ3 ZZ4

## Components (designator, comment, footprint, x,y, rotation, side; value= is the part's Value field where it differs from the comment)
C1 "C1005NP01H102J050BA" 0402 945,3930 r0 bottom
C2 "C1608X5R1H224K080AB" 0603 1279.77,3500 r270 bottom
C3 "C1608X6S1H474K080AB" 0603 1026.5,3120 r0 bottom
C4 "C1608X5R1V475K080AC" 0603 1419.77,3500 r90 bottom
C5 "C1608X5R1H224K080AB" 0603 1348.35,3500 r270 bottom
C6 "TPSD106K035R0125" 7343-31 1280,3250 r270 bottom
C7 "GRM155R71C104KA88D" 0402 1450,3346.54 r90 bottom
C8 "GRM155R71C104KA88D" 0402 1100,3232.36 r180 bottom
C9 "GRM155R71C104KA88D" 0402 1100,3370 r180 bottom
C10 "CGA3E2NP01H100D080AA" 0603 1474.61,3786.98 r270 top
C11 "CGA3E2NP01H100D080AA" 0603 1340.2,3786.98 r270 top
C12 "160R07X104KV4T" 0402_065 2281.1,1120 r90 top
C13 "GRM155R71C104KA88D" 0402 2135,356.38 r270 bottom
C14 "160R07X104KV4T" 0402_065 2321.1,1120 r90 top
C15 "160R07X104KV4T" 0402_065 2400.79,1120 r90 top
C16 "GRM155R71C104KA88D" 0402 2965,356.38 r270 bottom
C17 "160R07X104KV4T" 0402_065 2360.79,1120 r90 top
C18 "GRM155R61C103KA01D" 0402 2683.62,2048.87 r0 bottom
C19 "C1005X5R1A104K050BA" 0402 2410,1535 r0 bottom
C20 "C1005X5R1A104K050BA" 0402 2525,1620 r180 bottom
C21 "C1005X5R1A104K050BA" 0402 2300,1590 r0 bottom
C22 "C1005X5R1A104K050BA" 0402 2300,1750 r0 bottom
C23 "GRM155R61C105MA12D" 0402 2321.38,1495 r180 bottom
C24 "GRM155R61C105MA12D" 0402 2525,1580 r180 bottom
C25 "GRM155R61C103KA01D" 0402 2683.62,1997.37 r0 bottom
C26 "GRM155R61C105MA12D" 0402 2300,1550 r0 bottom
C27 "GRM155R61C105MA12D" 0402 2300,1710 r0 bottom
C28 "C1005X5R1A104K050BA" 0402 2525,1700 r180 bottom
C29 "C1005X5R1A104K050BA" 0402 2275,1670 r0 bottom
C30 "C1005X5R1A104K050BA" 0402 2472.9,1850 r90 bottom
C31 "GRM155R61C103KA01D" 0402 2423.62,2095.59 r0 bottom
C32 "GRM155R61C105MA12D" 0402 2525,1660 r180 bottom
C33 "GRM155R61C105MA12D" 0402 2275,1630 r0 bottom
C34 "GRM155R61C105MA12D" 0402 2514,1850 r90 bottom
C35 "GRM155R61C103KA01D" 0402 2423.62,2042.59 r0 bottom
C36 "GRM155R61C103KA01D" 0402 2423.75,2180 r0 bottom
C37 "C1005X5R1A104K050BA" 0402 2190,1469 r0 bottom
C38 "C1005X5R1A104K050BA" 0402 2190,1871 r0 bottom
C39 "GRM155R61C105MA12D" 0402 2190,1429 r0 bottom
C40 "GRM155R61C105MA12D" 0402 2190,1831 r0 bottom
C41 "GRM21BC80G476ME15L" 0805_HV 2060,2010 r180 bottom
C42 "C0402C103J5RACTU" 0402 2820,1645.08 r270 bottom
C43 "C0402C102J3RACTU" 0402 2872.42,1645.08 r270 bottom
C44 "CC0402JRNPO9BN101" 0402 2790,1476.38 r90 bottom
C45 "CGA3E2C0G1H220J080AA" 0603 2433.46,1280 r180 bottom
C46 "CGA3E2C0G1H220J080AA" 0603 2280,1403.94 r270 bottom
C47 "GRM155R61A333KA01D" 0402L 440,1491.22 r0 bottom
C48 "GRM155R61A333KA01D" 0402L 510.08,1531.38 r0 bottom
C49 "C0603C104K8RACTU" 0603 1681.14,1816.77 r180 bottom
C50 "GRM155R61A333KA01D" 0402L 440,1571.54 r0 bottom
C51 "C0603C104K8RACTU" 0603 1681.14,1699.84 r180 bottom
C52 "GRM155R61A333KA01D" 0402L 510.08,1692.01 r0 bottom
C53 "GRM155R61A333KA01D" 0402L 510.08,1611.69 r0 bottom
C54 "C0603C104K8RACTU" 0603 1681.14,1582.91 r180 bottom
C55 "GRM155R61A333KA01D" 0402L 440,1651.85 r0 bottom
C56 "GRM155R61A333KA01D" 0402L 440,1732.17 r0 bottom
C57 "C0603C104K8RACTU" 0603 1681.14,1465.98 r180 bottom
C58 "GRM155R61A333KA01D" 0402L 490.39,1792.01 r90 bottom
C59 "GR442QR73D102KW01L" 1808 600.94,1300 r180 bottom
C60 "1812GC472KAT1A" 1812_254 1300,180 r90 bottom
C61 "1812GC472KAT1A" 1812_254 1520,180 r90 bottom
C62 "1812GC472KAT1A" 1812_254 1520,180 r90 top
C63 "1812GC472KAT1A" 1812_254 1300,180 r90 top
C64 "1812GC472KAT1A" 1812_254 320,2470 r270 bottom
C65 "1812GC472KAT1A" 1812_254 320,2470 r270 top
C66 "1812GC472KAT1A" 1812_254 597,2150 r180 top
C67 "1812GC472KAT1A" 1812_254 597,2160 r180 bottom
C68 "CGA6P1X7R1E106M250AC" 1210_280 820,2788.11 r270 top
C69 "CGA6P1X7R1C226M250AC" 1210_280 620,2873.07 r270 bottom
C70 "CGA6P1X7R1E106M250AC" 1210_280 620,3100 r90 bottom
C71 "GRM216R61C105KA88D" 0805_HV 760,3075.04 r90 bottom
C72 "GCM21BR71H104KA37K" 0805_HV 800,2938.03 r0 bottom
C73 "CGA2B3X7R1H103K050BB" 0402 850,3014.49 r90 top
C74 "CGA2B3X7R1H103K050BB" 0402 1410,737.24 r90 bottom
C75 "GRM155R71C104KA88D" 0402 1370,737.24 r90 bottom
C76 "CGA3E1X7S1C225M080AC" 0603 2121.61,3234.09 r90 bottom
C77 "GRM155R6YA105ME11D" 0402 1860,3238.03 r270 bottom
C78 "C3216X7R1V106M160AC" 1206_190 2021.61,3340 r180 bottom
C79 "CL10B104KO8NNNC" 0603 2181.61,3234.09 r270 bottom
C80 "GRM155R61C105MA12D" 0402 2181.61,3340 r0 bottom
C81 "CGA2B3X7R1H103K050BB" 0402 1410,638.5 r270 bottom
C82 "GRM155R71C104KA88D" 0402 1370,638.5 r270 bottom
C83 "C3216X7R1V106M160AC" 1206_190 1490,605.2 r270 bottom
C84 "CGA6P1X7R1E106M250AC" 1210_280 300,2670.24 r270 bottom
C85 "CGA6P1X7R1C226M250AC" 1210_280 440,2670.24 r270 bottom
C86 "CGA3E1X7S1C225M080AC" 0603 3130,3380 r180 bottom
C87 "GRM155R6YA105ME11D" 0402 3131.97,3130 r0 bottom
C88 "C0603C103J5RACTU" 0603 3220,3891.5 r270 bottom
C89 "06035A102KAT2A" 0603 3160,3891.5 r270 bottom
C90 "CC0402JRNPO9BN101" 0402 3183.62,3780 r180 bottom
C91 "593D107X0010D2TE3" 7343-31 3360,3460.91 r270 bottom
C92 "293D475X9035D2TE3" 7343-31 1140,3694.53 r270 bottom
C93 "GRM155R71C104KA88D" 0402 1340,3790 r90 bottom
C94 "GRM155R61C105MA12D" 0402 3040,3820 r90 bottom
C95 "GRM155R61C105MA12D" 0402 2510,3790 r0 bottom
C96 "C1005X5R1A104K050BA" 0402 3080,3820 r90 bottom
C97 "C1005X5R1A104K050BA" 0402 2510,3750 r0 bottom
C98 "593D107X0010D2TE3" 7343-31 2350,3220 r270 bottom
C99 "GRM155R6YA105ME11D" 0402 2673.82,3087.28 r0 bottom
C100 "C0603C103J5RACTU" 0603 2490,3290 r90 bottom
C101 "06035A102KAT2A" 0603 2510,3601.5 r270 bottom
C102 "CC0402JRNPO9BN101" 0402 2510,3390 r180 bottom
C103 "GRM155R61E102KA01D" 0402 3080,3920 r270 bottom
C104 "GRM155R61E102KA01D" 0402 2610,3750 r180 bottom
C105 "C0603C103J5RACTU" 0603 2703.35,3387.28 r180 bottom
C106 "CGA3E1X7S1C225M080AC" 0603 2558.06,3290.91 r90 bottom
C107 "CC0402JRNPO9BN101" 0402 3040,3920 r270 bottom
C108 "CC0402JRNPO9BN101" 0402 2610,3790 r180 bottom
C109 "C3216X7R1V106M160AC" 1206_190 2980,3000 r90 bottom
C110 "C3216X7R1V106M160AC" 1206_190 2710,3720 r90 bottom
C111 "CL10B104KO8NNNC" 0603L 2830,3793 r180 bottom
C112 "C0603C103J5RACTU" 0603L 2960,3740 r180 bottom
C113 "06035A102KAT2A" 0603L 2830,3740 r0 bottom
C114 "CC0402JRNPO9BN101" 0402 2952.13,3790 r180 bottom
C115 "593D107X0010D2TE3" 7343-31 3240,2900 r270 bottom
C116 "0805YD105KAT2A" 0805_HV 3080,3000 r90 bottom
C117 "CC0805ZRY5V6BB475" 0805_HV 3000,3200 r90 bottom
C118 "CL10C270FB8NNNC" 0603L 2812.76,3240 r0 top
D1 "HSMF-C165" HSMF-C165_RG 1020,2820 r270 top
D2 "HSMF-C165" HSMF-C165_RG 1100,2820 r270 top
D3 "HSMF-C165" HSMF-C165_RG 1180,2820 r270 top
D4 "NRVBA160T3G" SMA 160,2813.94 r90 bottom
D5 "QTLP630C4TR" QTLP630C_Green 2050,2879.98 r270 top
D6 "QTLP630C4TR" QTLP630C_Green 2350,2881.3 r270 top
D7 "QTLP630C4TR" QTLP630C_Green 2640,2880 r270 top
D8 "QTLP630C4TR" QTLP630C_Green 2840,2880 r270 top
F1 "F0603E3R00FSTR" 0603 321.1,3380 r270 bottom
FID1 "Fiducial" Fiducial10-20 3460,3710 r0 top
FID2 "Fiducial" Fiducial10-20 160,350 r180 bottom
FID3 "Fiducial" Fiducial10-20 160,350 r0 top
FID4 "Fiducial" Fiducial10-20 3460,350 r180 bottom
FID5 "Fiducial" Fiducial10-20 3460,350 r0 top
FID6 "Fiducial" Fiducial10-20 3460,3710 r180 bottom
H1 "U77-A1118-200T" Amphenol_U77-A1118-200T 1298.27,680 r0 top
J1 "TSW-102-07-G-D" TSW-102-07-G-D 1800,3420 r0 top
J2 "HTSW-103-07-G-S" Samtec_HTSW-103-07-G-S 2080,2610 r180 top
J3 "1367073-1" TE_1367073-1 1333.7,680 r0 top
J4 "HTSW-103-07-G-S" Samtec_HTSW-103-07-G-S 2560,2610 r180 top
J5 "901-143-6RFX" Amphenol_901-143-6RFX 1940,190 r270 bottom
J6 "HTSW-102-07-G-S" Samtec_HTSW-102-07-G-S 3010,1350 r180 top
J7 "HTSW-103-07-G-S" Samtec_HTSW-103-07-G-S 3040,2610 r180 top
J8 "HTSW-102-07-G-S" Samtec_HTSW-102-07-G-S 3070,2270 r90 top
J9 "901-143-6RFX" Amphenol_901-143-6RFX 2330,190 r270 top
J10 "HTSW-102-07-G-S" Samtec_HTSW-102-07-G-S 3020,1820 r180 top
J11 "HTSW-102-07-G-S" Samtec_HTSW-102-07-G-S 3020,2020 r180 top
J12 "901-143-6RFX" Amphenol_901-143-6RFX 3160,190 r270 top
J13 "901-143-6RFX" Amphenol_901-143-6RFX 2770,190 r270 bottom
J14 "PRPC015DAAN-RC" Sullins_xxPC015DAAN-RC 3480,1670 r0 top
J15 "90122-0763" Molex_90122-0763 1780,3840 r270 top
J16 "CLKOUT" Samtec_MCX-J-P-H-ST-SM1 2040,1120 r90 top
J17 "TSW-104-07-G-D" TSW-104-07-G-D 2990,820 r0 top
J18 "EXT_REF_CLK" Samtec_MCX-J-P-H-ST-SM1 2620,1000 r0 top
J19 "HTSW-102-07-G-S" Samtec_HTSW-102-07-G-S 2680,1260 r0 top
J20 "1-406541-1" TEC_1-406541-1 315,1631.38 r270 top
J21 "HTSW-103-07-G-S" Samtec_HTSW-103-07-G-S 2410,3570 r90 top
J22 "HTSW-103-07-G-S" Samtec_HTSW-103-07-G-S 520,3340 r0 top
J23 "HTSW-103-07-G-S" Samtec_HTSW-103-07-G-S 2210,3570 r90 top
J24 "1502-2" Keystone1502-2 120,3340 r90 top
J25 "5V MIN, 20V MAX" CUI_PJ-037AH 520,3640 r180 top
J26 "HTSW-102-07-G-S" Samtec_HTSW-102-07-G-S 1020,2540 r180 top
J27 "HTSW-103-07-G-S" Samtec_HTSW-103-07-G-S 2010,3570 r90 top
J28 "HTSW-103-07-G-S" Samtec_HTSW-103-07-G-S 3010,3570 r90 top
J29 "1502-2" Keystone1502-2 120,3660 r0 top
J30 "GND" Keystone1502-2 1480,2320 r0 top
J31 "GND" Keystone1502-2 3440,2880 r0 top
J32 "475890001" Molex_0475890001 1420,4060 r0 bottom
J33 "HTSW-103-07-G-S" Samtec_HTSW-103-07-G-S 3210,3570 r90 top
J34 "HTSW-103-07-G-S" Samtec_HTSW-103-07-G-S 880,3570 r270 top
J35 "HTSW-103-07-G-S" Samtec_HTSW-103-07-G-S 2610,3570 r90 top
J36 "HTSW-103-07-G-S" Samtec_HTSW-103-07-G-S 2810,3570 r90 top
L1 "IFSC0806AZER1R0M01" IFSC-0806AZ-01 1280,737.24 r0 bottom
L2 "IFSC0806AZER1R0M01" IFSC-0806AZ-01 1280,638.5 r0 bottom
LBL1 "THT-14-423-10" Label_650x200 700,160 r0 top
LD1 "QTLP630C4TR" QTLP630C_Green 1980,2450 r90 top
LD2 "QTLP630C4TR" QTLP630C_Green 2180,2450 r90 top
LD3 "QTLP630C4TR" QTLP630C_Green 2460,2450 r90 top
LD4 "QTLP630C4TR" QTLP630C_Green 2660,2450 r90 top
LD5 "QTLP630C4TR" QTLP630C_Green 2940,2450 r90 top
LD6 "QTLP630C4TR" QTLP630C_Green 3140,2450 r90 top
Logo1 "CE Mark" CE_Mark_5mm 3180,560 r0 top
Logo2 "Texas Instruments" TI_Stacked_Overlay_Small 2230,720 r0 top
Logo3 "FCC disclaimer" FCC_disclaimer 2327.39,540 r0 top
Logo4 "WEEE logo" WEEE_Minimum 3480,600 r0 top
M1 "TESTPOINT" TESTPOINT 160,160 r0 top
M2 "TESTPOINT" TESTPOINT 3460,3900 r0 top
M3 "TESTPOINT" TESTPOINT 3460,160 r0 top
M4 "TESTPOINT" TESTPOINT 160,3900 r0 top
P1 "TSW-108-07-G-D" TSW-108-07-G-D 2610,3920 r0 top
R1 "CRCW0402470RJNED" 0402 1000,2960 r90 top
R2 "CRCW0402470RJNED" 0402 1040,2960 r90 top
R3 "CRCW0402470RJNED" 0402 1080,2960 r90 top
R4 "CRCW0402470RJNED" 0402 1120,2960 r90 top
R5 "CRCW0402470RJNED" 0402 1160,2960 r90 top
R6 "CRCW0402470RJNED" 0402 1200,2960 r90 top
R7 "CRCW04022K49FKED" 0402 1670,2780 r90 bottom
R8 "CRCW04022K49FKED" 0402 1570,2780 r90 bottom
R9 "CRCW04022K49FKED" 0402 1470,2780 r90 bottom
R10 "CRCW04022K49FKED" 0402 1370,2780 r90 bottom
R11 "CRCW04020000Z0ED" 0402 1164.77,3720 r0 top
R12 "CRCW040247K0JNED" 0402 945,3870 r0 bottom
R13 "CRCW04021K40FKED" 0402 1452.71,3705 r180 top
R14 "CRCW04021M00FKED" 0402 1544.53,3650 r0 top
R15 "CRCW04020000Z0ED" 0402 1076.38,3300 r90 bottom
R16 "CRCW040227R0JNED" 0402 1387.72,3775 r90 top
R17 "CRCW040227R0JNED" 0402 1427.09,3775 r90 top
R18 "RC0603FR-07470RL" 0603 1980,2450 r270 bottom
R19 "CRCW04022K49FKED" 0402 2040,2505.12 r270 bottom
R20 "CRCW04022K49FKED" 0402 2120,2505.12 r270 bottom
R21 "RC0603FR-07470RL" 0603 2180,2450 r270 bottom
R22 "ERJ-2GE0R00X" 0402 1860,480 r0 bottom
R23 "CRCW04026K04FKED" 0402 1860,420 r180 bottom
R24 "RC0603FR-07470RL" 0603 2460,2450 r270 bottom
R25 "CRCW04022K49FKED" 0402 2520,2505.12 r270 bottom
R26 "CRCW04024K70JNED" 0402 1050,780 r270 bottom
R27 "CRCW04022K49FKED" 0402 2600,2505.12 r270 bottom
R28 "RC0603FR-07470RL" 0603 2660,2450 r90 bottom
R29 "RC0603FR-07470RL" 0603 2940,2450 r270 bottom
R30 "CRCW04022K49FKED" 0402 2983.62,1420 r0 bottom
R31 "MCR01MZPJ000" 0402 2220,1230 r180 bottom
R32 "CRCW04022K49FKED" 0402 3000,2505.12 r270 bottom
R33 "CRCW04026K04FKED" 0402 2650,1679.21 r0 bottom
R34 "CRCW040249R9FKED" 0402L 2097,380 r0 top
R35 "CRCW04022K49FKED" 0402 3140,2296.38 r270 bottom
R36 "RC0603FR-07470RL" 0603 3140,2450 r90 bottom
R37 "CRCW04022K49FKED" 0402 3080,2505.12 r270 bottom
R38 "MCR01MZPJ000" 0402 2220,1180 r180 bottom
R39 "CRCW040249R9FKED" 0402L 2173,380 r0 top
R40 "CRCW04026K04FKED" 0402 2650,1718.9 r0 bottom
R41 "CRCW04022K49FKED" 0402 2650,1639.21 r180 bottom
R42 "CRCW04022K49FKED" 0402 2993.62,1890 r0 bottom
R43 "CRCW04022K49FKED" 0402 2650,1758.9 r180 bottom
R44 "CRCW04022K49FKED" 0402 3000,2120 r0 bottom
R45 "MCR01MZPJ000" 0402 2400.79,1120 r270 bottom
R46 "CRCW040249R9FKED" 0402L 3003,380 r180 top
R47 "MCR01MZPJ000" 0402 2360.79,1120 r270 bottom
R48 "CRCW040249R9FKED" 0402L 2927,380 r180 top
R49 "RC0402JR-070RL" 0402 3296.38,2370 r180 bottom
R50 "RC0402JR-070RL" 0402 3296.38,2270 r180 bottom
R51 "RC0402JR-070RL" 0402 3296.38,2170 r180 bottom
R52 "RC0402JR-070RL" 0402 3296.38,2070 r180 bottom
R53 "RC0402JR-070RL" 0402 3296.38,1970 r180 bottom
R54 "RC0402JR-070RL" 0402 3296.38,1870 r180 bottom
R55 "RC0402JR-070RL" 0402 3296.38,1770 r180 bottom
R56 "RC0402JR-070RL" 0402 3296.38,1670 r180 bottom
R57 "RC0402JR-070RL" 0402 3296.38,1570 r180 bottom
R58 "RC0402JR-070RL" 0402 3300,1470 r180 bottom
R59 "RC0402JR-070RL" 0402 3296.38,1370 r180 bottom
R60 "RC0402JR-070RL" 0402 3296.38,1270 r180 bottom
R61 "RC0402JR-070RL" 0402 3296.38,1170 r180 bottom
R62 "RC0402JR-070RL" 0402 3296.38,1070 r180 bottom
R63 "ERJ-1GN0R00C" 0201 2180,1753.27 r180 bottom
R64 "ERJ-1GN0R00C" 0201 2180,1723.58 r180 bottom
R65 "ERJ-1GN0R00C" 0201 2150,1694.21 r180 bottom
R66 "ERJ-1GN0R00C" 0201 2150,1664.53 r180 bottom
R67 "ERJ-1GN0R00C" 0201 2150,1635.16 r180 bottom
R68 "ERJ-1GN0R00C" 0201 2150,1605.47 r180 bottom
R69 "ERJ-1GN0R00C" 0201 2180,1576.1 r180 bottom
R70 "ERJ-1GN0R00C" 0201 2180,1546.42 r180 bottom
R71 "MCR01MZPJ000" 0402 2190,1509 r180 bottom
R72 "MCR01MZPJ000" 0402 2190,1791 r180 bottom
R73 "CRCW020111K0FKED" 0201M 2220,1490.49 r90 top
R74 "ERJ-1GNJ220C" 0201M 2545,1420 r270 top
R75 "TNPW06032K21BEEA" TNPW0603 2465,1845 r0 top
R76 "RC0402JR-070RL" 0402 1660,3380 r270 bottom
R77 "CRCW02012K20JNED" 0201M 2310,1960 r90 bottom
R78 "RC0402JR-070RL" 0402 1620,3321.1 r0 top
R79 "RC0402JR-070RL" 0402 1620,3380 r270 bottom
R80 "CRCW02012K20JNED" 0201M 1940,2140 r90 bottom
R81 "ERJ-2RKF1000X" 0402 2500,1400 r270 top
R82 "ERJ-2GEJ101X" 0402 2180,1972.98 r270 bottom
R83 "ERJ-1GN0R00C" 0201 2425,1845.28 r270 bottom
R84 "RC0402JR-070RL" 0402 1620,3281.42 r0 top
R85 "CRCW02014K70FKED" 0201_033 2580,1495.04 r90 bottom
R86 "ERJ-1GN0R00C" 0201 2439.53,1440 r90 top
R87 "ERJ-1GN0R00C" 0201 2698.5,1380 r180 bottom
R88 "CRCW04022K49FKED" 0402 2345,1870 r90 bottom
R89 "ERJ-1GN0R00C" 0201 2399.84,1440 r90 top
R90 "CRCW04022K49FKED" 0402 3040,980 r90 bottom
R91 "RC0402FR-071ML" 0402 2419.68,1378 r180 top
R92 "CRCW04022K49FKED" 0402 3140,980 r90 bottom
R93 "CRCW04022K49FKED" 0402 2820,1283.62 r90 bottom
R94 "ERJ-1GN0R00C" 0201 2500,1500 r180 bottom
R95 "ERJ-1GN0R00C" 0201 2500,1540 r0 bottom
R96 "CRCW080575R0FKEA" 0805_HV 723.61,1766.42 r0 bottom
R97 "CRCW080575R0FKEA" 0805_HV 723.61,1649.49 r0 bottom
R98 "CRCW080575R0FKEA" 0805_HV 723.61,1532.56 r0 bottom
R99 "CRCW080575R0FKEA" 0805_HV 723.61,1415.63 r0 bottom
R100 "HVCB2010FKC1M00" 2010 585.19,2350 r0 top
R101 "HVCB2010FKC1M00" 2010 585.19,2350 r0 bottom
R102 "CRCW06034K22FKEA" 0603 780,3022.36 r270 top
R103 "RT0603BRD071K35L" 0603 780,3180 r270 top
R104 "CRCW040210K0FKED" 0402 1920,3238.03 r90 bottom
R105 "ERJ-6GEY0R00V" 0805_HV 3110,3530 r270 bottom
R106 "CRCW040210K0FKED" 0402 3131.97,3190 r180 bottom
R107 "CRCW0402750RJNED" 0402 2050,3020 r90 bottom
R108 "CRCW0402470RJNED" 0402 2300,2980 r90 bottom
R109 "CRCW0402470RJNED" 0402 2580,2980 r90 bottom
R110 "CRCW0402470RJNED" 0402 2900,2976.33 r90 bottom
R111 "ERJ-6GEY0R00V" 0805_HV 2710,3530 r270 bottom
R112 "CRCW040233R0JNED" 0402 1160,4000 r180 bottom
R113 "CRCW040210K0FKED" 0402 2673.82,3147.28 r180 bottom
R114 "RC0603FR-0710KL" 0603 2960,3200 r270 top
R115 "ERJ-6GEY0R00V" 0805_HV 2910,3530 r270 bottom
R116 "CRCW040210K0FKED" 0402 2864.25,3086.93 r180 bottom
R117 "CRCW06031K13FKEA" 0603 2911.5,3320 r0 bottom
R118 "RC0603JR-070RL" 0603 2230,1420 r180 top
R119 "RC0603JR-070RL" 0603 2230,1840 r180 top
R120 "CRCW06034K53FKEA" 0603 2780,3288.5 r90 bottom
S1 "219-4LPST" SW_219-4LPST 1520,2780 r270 top
S2 "KSR221GLFS" KSR 920,3900 r0 top
S3 "KSR221GLFS" KSR 1940,2100 r90 top
SH1 "969102-0000-DA" SNT-100-BK-G 2810,3520 r90 top
SH2 "969102-0000-DA" SNT-100-BK-G 3010,3520 r90 top
SH3 "969102-0000-DA" SNT-100-BK-G 3210,3520 r90 top
SH4 "969102-0000-DA" SNT-100-BK-G 570,3340 r180 top
SH5 "969102-0000-DA" SNT-100-BK-G 2010,3520 r90 top
SH6 "969102-0000-DA" SNT-100-BK-G 2210,3520 r90 top
SH7 "969102-0000-DA" SNT-100-BK-G 2410,3520 r90 top
SH8 "969102-0000-DA" SNT-100-BK-G 2610,3520 r90 top
SH9 "969102-0000-DA" SNT-100-BK-G 880,3520 r90 top
SH10 "969102-0000-DA" SNT-100-BK-G 3090,2610 r180 top
SH11 "969102-0000-DA" SNT-100-BK-G 2610,2610 r180 top
SH12 "969102-0000-DA" SNT-100-BK-G 2130,2610 r180 top
SH13 "969102-0000-DA" SNT-100-BK-G 3070,2270 r90 top
T1 "HX5008NL" PULSE_HX5008NL 1240,1630 r180 top
T2 "ACM9070-701-2PL-TL01" TDK_ACM9070 390,3060 r270 bottom
TP1 "GND" Keystone_5019 2470,2230 r0 top
TP2 "GND" Keystone_5019 2190,2230 r0 top
TP3 "IO" Keystone_5019 2540,2050 r90 top
TP4 "1.0V" Keystone_5019 2400,2050 r90 top
TP5 "1.8V" Keystone_5019 2120,2050 r90 top
TP6 "2.5V" Keystone_5019 2260,2050 r90 top
TP7 "TESTPOINT" TP_25MIL-SMT 2180,1505.45 r90 top
U1 "MSP430F5529IPN" PN0080A_N 1259.77,3380 r0 top
U2 "DP83869EMRGZT" RGZ0048B 2400,1640 r0 top
U3 "SG-210STF 25.0000ML3" Epson_SG-210 2680,1474.41 r90 bottom
U4 "TPD4E05U06DQAR" DQA0010A 1760,1532.56 r0 top
U5 "TPD4E05U06DQAR" DQA0010A 1760,1766.42 r0 top
U6 "TL1963AQKTTRQ1" KTT0005A_N 380,2920 r180 top
U7 "TPS73733DRVR" DRV0006A 2021.61,3240 r180 bottom
U8 "TPS70933DRVR" DRV0006A 3130,3290 r270 bottom
U9 "TPS73525DRBR" DRB0008A 2659.06,3267.28 r270 bottom
U10 "TPS74701DRCR" DRC0010J 2880,3200 r90 bottom
XTAL1 "ECS-250-12-33Q-JES-TR" ECS_ECS-33Q 2419.68,1400 r270 bottom
Y1 "CSTCR4M00G55B-R0" Murata_CSTCR_G 1200.2,3810 r180 top
ZZ1 "This Assembly Note is for PCB labels only" AssemblyNoteLabel 157,4522 r0 top
ZZ2 "These assemblies are ESD sensitive, ESD precautions shall be observed." AssemblyNote 157,4702 r0 top
ZZ3 "These assemblies must be clean and free from flux and all contaminants. Use of no clean flux is not acceptable." AssemblyNote 157,4882 r0 top
ZZ4 "These assemblies must comply with workmanship standards IPC-A-610 Class 2, unless otherwise specified." AssemblyNote 157,5062 r0 top

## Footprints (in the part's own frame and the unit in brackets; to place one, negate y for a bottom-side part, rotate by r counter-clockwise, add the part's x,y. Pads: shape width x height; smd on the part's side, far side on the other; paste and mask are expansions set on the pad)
0201 [mm] "Data from Kemet datasheet CC101_COM dated 7/28/11"
  rect 0.46x0.42 smd mask+0.048: 1(-0.33,0) 2(0.33,0)
  body extent -0.31,-0.16 0.31,0.16, height 0.26
0201_033 [mm] "SMD, 2-Leads, Height 0.33mm"
  rect 0.46x0.42 smd mask+0.048: 1(-0.33,0) 2(0.33,0)
  body extent -0.31,-0.16 0.31,0.16, height 0.33
0201M [mm] "Data from Kemet datasheet CC101_COM dated 7/28/11"
  rect 0.56x0.52 smd mask+0.048: 1(-0.38,0) 2(0.38,0)
  body extent -0.31,-0.16 0.31,0.16, height 0.26
0402 [mm] "0402 from SM-752 data"
  rect 0.8x0.6 smd: 1(-0.6,0) 2(0.6,0)
  silkscreen extent -1.22,-0.52 1.22,0.52, body extent -0.55,-0.3 0.55,0.3, height 0.6
0402_065 [mm] "0402"
  rect 0.8x0.6 smd: 1(-0.6,0) 2(0.6,0)
  silkscreen extent -1.22,-0.52 1.22,0.52, body extent -0.55,-0.3 0.55,0.3, height 0.65
0402L [mm] "0402 from SM-752 data"
  rect 0.6x0.5 smd: 1(-0.5,0) 2(0.5,0)
  body extent -0.55,-0.3 0.55,0.3, height 0.6
0603 [mm] "0603 from SM-752 data"
  rect 1x0.95 smd: 1(-0.8,0) 2(0.8,0)
  silkscreen extent -1.52,-0.69 1.52,0.69, body extent -0.87,-0.47 0.87,0.47, height 1
0603L [mm] "0603 from SM-752 data"
  rect 0.8x0.85 smd: 1(-0.7,0) 2(0.7,0)
  silkscreen extent -0.07,-0.33 0.07,0.33, body extent -0.87,-0.47 0.87,0.47, height 1
0805_HV [mil] "0805 with 30mil clearance between pads"
  rect 50x63 smd: 1(-40,0) 2(40,0)
  silkscreen extent -74,-40 74,40, body extent -43,-29 43,29, height 57
1206_190 [mm] "1206_190"
  rect 1.1x1.6 smd: 1(-1.7,0) 2(1.7,0)
  silkscreen extent -0.9,-1 0.9,1, body extent -1.75,-0.95 1.75,0.95, height 1.9
1210_280 [mm] "SMD, 2-Leads, Body 3.6x2.8mm, Height 2.8mm"
  rect 1.1x2.2 smd: 1(-1.65,0) 2(1.65,0)
  silkscreen extent -0.84,-1.4 0.84,1.4, body extent -1.8,-1.4 1.8,1.4, height 2.8
1808 [mm] "Chip Capacitor, Body 4.6x2.0mm, IPC Medium Density"
  rect 1.4x2.3 smd: 1(-2.1,0) 2(2.1,0)
  silkscreen extent -3.1,-1.45 3.1,1.45, body extent -2.47,-1.2 2.47,1.2, height 2.03
1812_254 [mm] "SMD, 2-Leads, Body 4.8x3.4mm"
  rect 1.6x3.4 smd: 1(-2,0) 2(2,0)
  silkscreen extent -0.8,-1.7 0.8,1.7, body extent -2.4,-1.7 2.4,1.7, height 2.54
2010 [mm] "Chip Capacitor, Body 5.08x2.54mm, IPC Medium Density"
  rect 1.6x2.7 smd: 1(-2.3,0) 2(2.3,0)
  silkscreen extent -3.42,-1.65 3.42,1.65, body extent -2.73,-1.45 2.73,1.45, height 1.66
7343-31 [mm] "Medium Density based on Kemet T495 dimensions"
  rect 2.55x2.45 smd: 1(-3.025,0) 2(3.025,0)
  silkscreen extent -4.56,-2.3 3.8,2.3, body extent -3.8,-2.3 3.8,2.3, height 3.1
Amphenol_901-143-6RFX [mm] "SMA Jack, 50 Ohm, R/A, TH"
  rrect50% 2x2 hole 1.5: 1(0,0)
  round 2.2 hole 1.7: 2(-2.54,2.54) 3(2.54,2.54) 4(2.54,-2.54) 5(-2.54,-2.54)
  silkscreen extent -3.5,-3.5 3.5,3.5, body extent -3.5,-3.5 11.6,3.5, height 9.86
Amphenol_U77-A1118-200T [mm] "EMI SHIELD, 42.3x16.25 mm, SMT"
  round 1.45 hole 0.95: 1(-7.2,7.125) 2(-2.5,7.125) 3(2.5,7.125) 4(7.1,4.8) 5(7.1,0) 6(7.1,-4.8) 7(2.5,-7.125) 8(-2.5,-7.125) 9(-7.2,-7.125)
  rect 2x2 hole 1.05: 10(-10,1.445) 11(-10,-3.955) 12(-30,-1.455) MH1(-30,7.125) MH2(-20,7.125) MH3(-10,7.125) MH5(5,-7.125) MH6(-5,-7.125) MH7(-15,-7.125) MH8(-25,-7.125)
  rect 2x2 hole 0.85: MH4(0,7.125)
  silkscreen extent -41.18,-7.5 7.8,7.5, body extent -41.18,-7.92 7.8,7.93, height 9.97
AssemblyNote [mil] "Assembly Note"
AssemblyNoteLabel [mil] "Assembly Note for PCB Labels"
CE_Mark_5mm [mil] "Minimum text height for CE Mark"
  silkscreen extent -138,-98 138,98
CUI_PJ-037AH [mm] "Power Jack, 2mm, R/A, TH"
  oval 4.1x1.6 hole 1 slot 3.5 at 0 deg: 1(0,3)
  oval 3.6x1.6 hole 1 slot 3 at 0 deg: 2(0,-3)
  silkscreen extent -4.5,-10.3 4.5,3.8, body extent -4.5,-10.7 4.5,3.8, height 11
DQA0010A [mm] "SON, 10-Leads, Body 1x2.5mm, Pitch 0.5mm, TI Recommended"
  rrect50% 0.565x0.2 smd: 1(-0.417,1) 2(-0.417,0.5) 4(-0.417,-0.5) 5(-0.417,-1) 6(0.417,-1) 7(0.417,-0.5) 9(0.417,0.5) 10(0.417,1)
  rrect28% 0.565x0.36 on Top Paste: 3(-0.417,0) 8(0.417,0)
  rrect25% 0.565x0.4 smd paste-0.2: 3(-0.417,0) 8(0.417,0)
  silkscreen extent -0.67,-1.45 0.55,1.45, body extent -0.55,-1.3 0.55,1.3, height 0.56
DRB0008A [mm] "SON, 8-Leads, Body 3x3mm, Pitch 0.65mm, Thermal Pad 1.75x1.5mm, TI Recommended"
  rrect33% 0.6x0.3 smd: 1(-1.4,0.975) 2(-1.4,0.325) 3(-1.4,-0.325) 4(-1.4,-0.975) 5(1.4,-0.975) 6(1.4,-0.325) 7(1.4,0.325) 8(1.4,0.975)
  rrect7% 1.5x1.75 smd paste-0.75: 9(0,0)
  Top Layer region: -0.465,-1.5 -0.465,-0.875 -0.75,-0.875 -0.75,0.875 -0.465,0.875 -0.465,1.5 -0.185,1.5 -0.185,0.875 0.185,0.875 0.185,1.5 0.465,1.5 0.465,0.875 0.75,0.875 0.75,-0.875 0.465,-0.875 0.465,-1.5 0.185,-1.5 0.185,-0.875 -0.185,-0.875 -0.185,-1.5
  silkscreen extent -1.73,-1.73 1.73,1.73, body extent -1.58,-1.57 1.57,1.58, height 1.01
DRC0010J [mm] "SON, 10-Leads, Body 3x3mm, Pitch 0.5mm, Thermal Pad 2.4x1.65mm, TI Recommended"
  rrect57% 0.7x0.35 smd paste-0.05 mask-0.05: 1(-1.4,1) 2(-1.4,0.5) 3(-1.4,0) 4(-1.4,-0.5) 5(-1.4,-1) 6(1.4,-1) 7(1.4,-0.5) 8(1.4,0) 9(1.4,0.5) 10(1.4,1)
  rrect40% 0.25x0.34 on Bottom Paste: 11(-0.25,-1.53) 11(-0.25,1.53) 11(0.25,-1.53) 11(0.25,1.53)
  rrect9% 1.5x1.06 on Bottom Paste: 11(0,-0.63) 11(0,0.63)
  rrect12% 1.65x2.4 smd paste-1 mask-2: 11(0,0)
  Top Layer region: -0.25,-1.1 0.25,-1.1 0.25,-1.75 -0.25,-1.75
  Top Layer region: -0.25,1.75 0.25,1.75 0.25,1.1 -0.25,1.1
  Top Layer region: -0.775,-1.25 -0.425,-1.25 -0.425,-1.65 -0.417,-1.688 -0.396,-1.721 -0.363,-1.742 -0.325,-1.75 -0.325,-1.75 -0.325,-1.75 -0.175,-1.75 -0.175,-1.75 -0.137,-1.742 -0.104,-1.721 -0.083,-1.688 -0.075,-1.65 -0.075,-1.65 -0.075,-1.25 0.075,-1.25 0.075,-1.65 0.083,-1.688 0.104,-1.721 0.137,-1.742 0.175,-1.75 0.175,-1.75 0.175,-1.75 0.325,-1.75 0.325,-1.75 0.363,-1.742 0.396,-1.721 0.417,-1.688 0.425,-1.65 0.425,-1.65 0.425,-1.25 0.775,-1.25 0.813,-1.242 0.846,-1.221 0.867,-1.188 0.875,-1.15 0.875,-1.15 0.875,1.15 0.867,1.188 0.846,1.221 0.813,1.242 0.775,1.25 0.775,1.25 0.425,1.25 0.425,1.65 0.417,1.688 0.396,1.721 0.363,1.742 0.325,1.75 0.325,1.75 0.175,1.75 0.137,1.742 0.104,1.721 0.083,1.688 0.075,1.65 0.075,1.65 0.075,1.25 -0.075,1.25 -0.075,1.65 -0.083,1.688 -0.104,1.721 -0.137,1.742 -0.175,1.75 -0.175,1.75 -0.325,1.75 -0.363,1.742 -0.396,1.721 -0.417,1.688 -0.425,1.65 -0.425,1.65 -0.425,1.25 -0.775,1.25 -0.813,1.242 -0.846,1.221 -0.867,1.188 -0.875,1.15 -0.875,1.15 -0.875,-1.15 -0.867,-1.188 -0.846,-1.221 -0.813,-1.242 -0.775,-1.25
  silkscreen extent -1.63,-1.63 1.63,1.63, body extent -1.5,-1.5 1.5,1.5, height 0.77
DRV0006A [mm] "SON, 6-Leads, Body 2x2mm, Pitch 0.65mm, Thermal Pad 1.6x1mm, TI Recommended"
  rrect33% 0.45x0.3 smd: 1(-0.975,0.65) 2(-0.975,0) 3(-0.975,-0.65) 4(0.975,-0.65) 5(0.975,0) 6(0.975,0.65)
  rrect14% 1x0.7 on Bottom Paste: 7(0,-0.45) 7(0,0.45)
  rrect10% 1x1.6 smd paste-0.5: 7(0,0)
  silkscreen extent -1.05,-1.2 1.05,1.2, body extent -1.05,-1.05 1.05,1.05, height 0.81
ECS_ECS-33Q [mm] "SMD, 4-Leads, Body 2.5x3.2mm"
  rrect9% 1.1x1.3 smd: 1(-0.9,1.15) 2(-0.9,-1.15) 3(0.9,-1.15) 4(0.9,1.15)
  silkscreen extent -1.75,0.6 -1.75,1.7, body extent -1.3,-1.65 1.3,1.65, height 0.81
Epson_SG-210 [mm] "SMD, 2-Leads, Body 2x2.5mm"
  rect 0.9x1.1 smd: 1(-0.65,0.85) 2(-0.65,-0.85) 3(0.65,-0.85) 4(0.65,0.85)
  silkscreen extent -1.4,-1.7 1.4,1.7, body extent -1.08,-1.33 1.08,1.33, height 0.91
FCC_disclaimer [mil]
Fiducial10-20 [mm]
  round 1 smd mask+0.5: 1(0,0)
  Top Layer keep-out circle w1.178: c0,0 r0.5
HSMF-C165_RG [mm] "SMD, 4-Leads, Body 1.6x0.8mm"
  rect 0.7x0.4 smd: 1(-0.65,0.35) 2(-0.65,-0.35) 3(0.65,0.35) 4(0.65,-0.35)
  silkscreen extent -1,-0.8 1.5,0.8, body extent -0.85,-0.45 0.85,0.45, height 0.51
IFSC-0806AZ-01 [mm] "Vishay-Dale"
  rect 0.85x1.7 smd: 1(-0.725,0) 2(0.725,0)
  body extent -1.1,-0.9 1.1,0.9, height 1
Keystone1502-2 [mm] "Double Turret"
  round 3.5 hole 2.5: 1(0,0)
  silkscreen extent -2.3,-2.3 2.3,2.3, body extent -1.6,-1.6 1.59,1.6, height 5.62
Keystone_5019 [mm] "Test Point, Miniature, SMT"
  rect 3.8x2.03 smd: 1(0,0)
  silkscreen extent -2.31,-1.42 2.31,1.42, body extent -1.9,-1.02 1.9,1.02, height 2.29
KSR [mm] "C&K Components SPST switch"
  rect 1.5x1.4 smd: 1(-3.25,0) 2(3.25,0)
  silkscreen extent -3.2,-2 3.2,2, body extent -3,-1.9 3,1.9, height 2.65
KTT0005A_N [mm] "D2-PAK, 6-Leads, Body 8.9x10.2mm, Pitch 1.7mm, Lead Span 15.2mm, IPC Medium Density"
  rrect10% 4.15x1 smd: 1(-6.25,3.4) 2(-6.25,1.7) 3(-6.25,0) 4(-6.25,-1.7) 5(-6.25,-3.4)
  rrect1% 8.2x10.75 smd: 6(4.2,0)
  silkscreen extent -6.43,-5.35 -0.3,5.35, body extent -7.63,-5.08 7.63,5.08, height 4.83
Label_650x200 [mil] "Thermal Transfer Label"
  round 1 on Mech13: 0(0,0)
  silkscreen extent -325,-100 325,100, body extent -325,-100 325,100, height 1
Molex_90122-0763 [mm] "Header, 2.54mm, 3x2, R/A, TH"
  rrect50% 1.5x1.5 hole 1: 1(-1.27,2.54)
  round 1.5 hole 1: 2(1.27,2.54) 3(-1.27,0) 4(1.27,0) 5(-1.27,-2.54) 6(1.27,-2.54)
  silkscreen extent -5.6,-3.9 -2.6,3.9, body extent -12.27,-3.81 1.57,3.81, height 6.35
Molex_0475890001 [mm] "Molex"
  rrect25% 0.4x1.35 smd: 1(-1.3,4.125) 2(-0.65,4.125) 3(0,4.125) 4(0.65,4.125) 5(1.3,4.125)
  oval 1.05x1.3 hole 0.7 slot 0.85 at 90 deg: 6(2.225,4.45) 11(-2.225,4.45)
  oval 0.854x2 hole 0.6 slot 1.3 at 90 deg: 7(4.175,1.45) 10(-4.175,1.45)
  rrect6% 1.8x2 smd: 8(1.15,1.45) 9(-1.15,1.45)
  Top Layer region: -4.175,0.45 -4.175,2.45 -2.6,2.45 -2.6,0.45
  Top Layer region: 2.6,0.45 2.6,2.45 4.175,2.45 4.175,0.45
  silkscreen extent -3.75,2.85 3.75,4.3, body extent -4.32,-1.3 4.33,4.59, height 2.81
Murata_CSTCR_G [mm] "Murata"
  rect 0.4x2.6 smd: 1(-1.5,0) 2(0,0) 3(1.5,0)
  Top Layer region: 1.1,-1.301 1.1,-0.801 1.9,-0.801 1.9,-1.301
  Top Layer region: 1.1,0.8 1.9,0.8 1.9,1.3 1.1,1.3
  Top Layer region: -1.9,-1.301 -1.9,-0.801 -1.1,-0.801 -1.1,-1.301
  Top Layer region: -1.9,0.8 -1.1,0.8 -1.1,1.3 -1.9,1.3
  Top Layer region: -0.4,-1.301 -0.4,-0.801 0.4,-0.801 0.4,-1.301
  Top Layer region: -0.4,0.8 0.4,0.8 0.4,1.3 -0.4,1.3
  body extent -2.25,-1 2.25,1, height 1.16
PN0080A_N [mm] "QFP, 80-Leads, Body 12x12mm, Pitch 0.5mm, IPC Medium Density"
  oval 1.45x0.3 smd: 1(-6.725,4.75) 2(-6.725,4.25) 3(-6.725,3.75) 4(-6.725,3.25) 5(-6.725,2.75) 6(-6.725,2.25) 7(-6.725,1.75) 8(-6.725,1.25) 9(-6.725,0.75) 10(-6.725,0.25) 11(-6.725,-0.25) 12(-6.725,-0.75) 13(-6.725,-1.25) 14(-6.725,-1.75) 15(-6.725,-2.25) 16(-6.725,-2.75) 17(-6.725,-3.25) 18(-6.725,-3.75) 19(-6.725,-4.25) 20(-6.725,-4.75) 41(6.725,-4.75) 42(6.725,-4.25) 43(6.725,-3.75) 44(6.725,-3.25) 45(6.725,-2.75) 46(6.725,-2.25) 47(6.725,-1.75) 48(6.725,-1.25) 49(6.725,-0.75) 50(6.725,-0.25) 51(6.725,0.25) 52(6.725,0.75) 53(6.725,1.25) 54(6.725,1.75) 55(6.725,2.25) 56(6.725,2.75) 57(6.725,3.25) 58(6.725,3.75) 59(6.725,4.25) 60(6.725,4.75)
  oval 0.3x1.45 smd: 21(-4.75,-6.725) 22(-4.25,-6.725) 23(-3.75,-6.725) 24(-3.25,-6.725) 25(-2.75,-6.725) 26(-2.25,-6.725) 27(-1.75,-6.725) 28(-1.25,-6.725) 29(-0.75,-6.725) 30(-0.25,-6.725) 31(0.25,-6.725) 32(0.75,-6.725) 33(1.25,-6.725) 34(1.75,-6.725) 35(2.25,-6.725) 36(2.75,-6.725) 37(3.25,-6.725) 38(3.75,-6.725) 39(4.25,-6.725) 40(4.75,-6.725) 61(4.75,6.725) 62(4.25,6.725) 63(3.75,6.725) 64(3.25,6.725) 65(2.75,6.725) 66(2.25,6.725) 67(1.75,6.725) 68(1.25,6.725) 69(0.75,6.725) 70(0.25,6.725) 71(-0.25,6.725) 72(-0.75,6.725) 73(-1.25,6.725) 74(-1.75,6.725) 75(-2.25,6.725) 76(-2.75,6.725) 77(-3.25,6.725) 78(-3.75,6.725) 79(-4.25,6.725) 80(-4.75,6.725)
  silkscreen extent -6.85,-5.6 5.6,5.6, body extent -7,-7 7,7, height 1.56
PULSE_HX5008NL [mm] "SMD, 24-Leads, Body 15.11x13.16mm, Pitch 0.99mm"
  rect 1.905x0.64 smd: 1(-8.828,5.445) 2(-8.828,4.455) 3(-8.828,3.465) 4(-8.828,2.475) 5(-8.828,1.485) 6(-8.828,0.495) 7(-8.828,-0.495) 8(-8.828,-1.485) 9(-8.828,-2.475) 10(-8.828,-3.465) 11(-8.828,-4.455) 12(-8.828,-5.445) 13(8.828,-5.445) 14(8.828,-4.455) 15(8.828,-3.465) 16(8.828,-2.475) 17(8.828,-1.485) 18(8.828,-0.495) 19(8.828,0.495) 20(8.828,1.485) 21(8.828,2.475) 22(8.828,3.465) 23(8.828,4.455) 24(8.828,5.445)
  silkscreen extent -8.95,-6.71 7.68,6.71, body extent -9.34,-6.7 9.34,6.71, height 6.63
QTLP630C_Green [mm] "SMT, 2-Leads, Body 2x1.25mm"
  rect 1.2x1.2 smd: 1(-1.05,0) 2(1.05,0)
  silkscreen extent -0.15,-0.8 2.15,0.8, body extent -1.1,-0.73 1.1,0.73, height 1.22
RGZ0048B [mm] "QFN, 48-Leads, Body 7x7mm, Pitch 0.5mm, Thermal Pad 5.15x5.15mm, TI Recommended"
  rrect42% 0.6x0.24 smd: 1(-3.4,2.75) 2(-3.4,2.25) 3(-3.4,1.75) 4(-3.4,1.25) 5(-3.4,0.75) 6(-3.4,0.25) 7(-3.4,-0.25) 8(-3.4,-0.75) 9(-3.4,-1.25) 10(-3.4,-1.75) 11(-3.4,-2.25) 12(-3.4,-2.75) 25(3.4,-2.75) 26(3.4,-2.25) 27(3.4,-1.75) 28(3.4,-1.25) 29(3.4,-0.75) 30(3.4,-0.25) 31(3.4,0.25) 32(3.4,0.75) 33(3.4,1.25) 34(3.4,1.75) 35(3.4,2.25) 36(3.4,2.75)
  rrect42% 0.24x0.6 smd: 13(-2.75,-3.4) 14(-2.25,-3.4) 15(-1.75,-3.4) 16(-1.25,-3.4) 17(-0.75,-3.4) 18(-0.25,-3.4) 19(0.25,-3.4) 20(0.75,-3.4) 21(1.25,-3.4) 22(1.75,-3.4) 23(2.25,-3.4) 24(2.75,-3.4) 37(2.75,3.4) 38(2.25,3.4) 39(1.75,3.4) 40(1.25,3.4) 41(0.75,3.4) 42(0.25,3.4) 43(-0.25,3.4) 44(-0.75,3.4) 45(-1.25,3.4) 46(-1.75,3.4) 47(-2.25,3.4) 48(-2.75,3.4)
  rrect9% 1.17x1.17 on Top Paste: 49(-1.37,-1.37) 49(-1.37,0) 49(-1.37,1.37) 49(0,-1.37) 49(0,0) 49(0,1.37) 49(1.37,-1.37) 49(1.37,0) 49(1.37,1.37)
  rrect2% 4.1x4.1 smd paste-2.575: 49(0,0)
  silkscreen extent -3.72,-3.72 3.72,3.72, body extent -3.5,-3.5 3.5,3.5, height 1.01
Samtec_HTSW-102-07-G-S [mm] "Samtec 100mil, 1x2, 230 mil above insulator"
  rrect6% 1.65x1.65 hole 1.016: 1(-1.27,0)
  round 1.65 hole 1.016: 2(1.27,0)
  silkscreen extent -2.54,-1.9 2.54,1.27, body extent -2.54,-1.27 2.54,1.27, height 8.38
Samtec_HTSW-103-07-G-S [mm] "Samtec 100mil, 1x3, 230 mil above insulator"
  rrect6% 1.65x1.65 hole 1.016: 1(-2.54,0)
  round 1.65 hole 1.016: 2(0,0) 3(2.54,0)
  silkscreen extent -4.57,-1.27 3.81,1.27, body extent -3.81,-1.27 3.81,1.27, height 8.38
Samtec_MCX-J-P-H-ST-SM1 [mm] "Samtec"
  round 1.65 smd: 1(0,0)
  rect 2.1x2.1 smd: 2(-2.22,2.22) 3(-2.22,-2.22) 4(2.22,-2.22) 5(2.22,2.22)
  silkscreen extent -3.1,-3.1 3.1,3.1, body extent -2.94,-2.94 2.94,2.94, height 6.02
SMA [mm] "Molded Diode, 2-Leads, Body 4.3x2.6mm, IPC Medium Density, based on OnSemi component dimensions and land pattern"
  rect 2x2 smd: 1(-2,0) 2(2,0)
  silkscreen extent -3.66,-1.57 2.79,1.57, body extent -2.6,-1.3 2.6,1.3, height 2.42
SNT-100-BK-G [mil] "Samtec STEP model"
  round 1 on Mech3: 0(0,0)
  body extent -100,-50 100,50, height 344
Sullins_xxPC015DAAN-RC [mm] "Header, 2.54mm, 15x2, TH"
  rrect50% 1.5x1.5 hole 1: 1(-1.27,17.78)
  round 1.5 hole 1: 2(1.27,17.78) 3(-1.27,15.24) 4(1.27,15.24) 5(-1.27,12.7) 6(1.27,12.7) 7(-1.27,10.16) 8(1.27,10.16) 9(-1.27,7.62) 10(1.27,7.62) 11(-1.27,5.08) 12(1.27,5.08) 13(-1.27,2.54) 14(1.27,2.54) 15(-1.27,0) 16(1.27,0) 17(-1.27,-2.54) 18(1.27,-2.54) 19(-1.27,-5.08) 20(1.27,-5.08) 21(-1.27,-7.62) 22(1.27,-7.62) 23(-1.27,-10.16) 24(1.27,-10.16) 25(-1.27,-12.7) 26(1.27,-12.7) 27(-1.27,-15.24) 28(1.27,-15.24) 29(-1.27,-17.78) 30(1.27,-17.78)
  body extent -2.5,-19.05 2.5,19.05, height 8.34
SW_219-4LPST [mil] "SMD, 8-Leads, Body 11.93x6.95mm, Pitch 2.54mm"
  rect 96x44 smd: 1(-169.5,150) 2(-169.5,50) 3(-169.5,-50) 4(-169.5,-150) 5(169.5,-150) 6(169.5,-50) 7(169.5,50) 8(169.5,150)
  silkscreen extent -171,-229 132,229, body extent -195,-229 195,229, height 169
TDK_ACM9070 [mm] "SMD, 4-Leads, Body 9x7mm"
  rrect7% 2.5x1.5 smd: 1(-4.25,1.75) 2(-4.25,-1.75) 3(4.25,-1.75) 4(4.25,1.75)
  silkscreen extent -4.77,-3.6 4.6,3.6, body extent -4.6,-3.6 4.6,3.6, height 4.5
TE_1367073-1 [mm] "SMD, 20-Leads, Body 11.2x7.4mm, Pitch 0.8mm"
  rect 2x0.5 smd: 1(-4.1,3.4) 2(-4.1,2.6) 3(-4.1,1.8) 4(-4.1,1) 5(-4.1,0.2) 6(-4.1,-0.6) 7(-4.1,-1.4) 8(-4.1,-2.2) 9(-4.1,-3) 10(-4.1,-3.8) 11(4.1,-3.4) 12(4.1,-2.6) 13(4.1,-1.8) 14(4.1,-1) 15(4.1,-0.2) 16(4.1,0.6) 17(4.1,1.4) 18(4.1,2.2) 19(4.1,3) 20(4.1,3.8)
  round 0 hole 1.55 unplated: MH1(0,4.8) MH2(0,-4.8)
  Top Layer keep-out region: -2.88,-3.85 2.88,-3.85 2.88,-3.99 3.94,-3.99 3.94,-5.75 -4.34,-5.75 -4.34,-4.39 -2.88,-4.39
  Top Layer keep-out region: -4.34,5.75 3.94,5.75 3.94,4.39 2.88,4.39 2.88,3.85 -2.88,3.85 -2.88,3.99 -4.34,3.99
  silkscreen extent -5.1,-5.7 4.8,5.7, body extent -4.5,-5.5 4.5,5.5, height 5.2
TEC_1-406541-1 [mm] "TE Connectivity"
  round 1.4 hole 0.89: 1(3.56,-0.18) 2(2.54,1.6) 3(1.52,-0.18) 4(0.5,1.6) 5(-0.52,-0.18) 6(-1.54,1.6) 7(-2.56,-0.18) 8(-3.58,1.6)
  round 2.1 hole 1.57: 9(8.12,0.71) 10(-8.14,0.71)
  round 3.759 hole 3.251: 11(6.34,-2.72) 12(-6.36,-2.72)
  silkscreen extent -9.69,-8 9.69,8.06, body extent -9.33,-8 9.31,7.75, height 14.8
TESTPOINT [mil]
  round 200 hole 126: 1(0,0)
TI_Stacked_Overlay_Small [mil]
  silkscreen extent -418,-98 418,98
TNPW0603 [mm] "Vishay"
  rect 0.5x0.9 smd: 1(-0.75,0) 2(0.75,0)
  silkscreen extent -0.2,-0.6 0.2,0.6, body extent -0.85,-0.47 0.85,0.47, height 0.55
TP_25MIL-SMT [mil]
  round 25 smd mask-2.5: 1(0,0)
TSW-102-07-G-D [mm] "Samtec 100mil, 2x2, 230 mil above insulator"
  rrect6% 1.65x1.65 hole 1.016: 1(-1.27,-1.27)
  round 1.65 hole 1.016: 2(-1.27,1.27) 3(1.27,-1.27) 4(1.27,1.27)
  silkscreen extent -2.54,-3.17 2.54,2.54, body extent -2.54,-2.54 2.54,2.54, height 8.38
